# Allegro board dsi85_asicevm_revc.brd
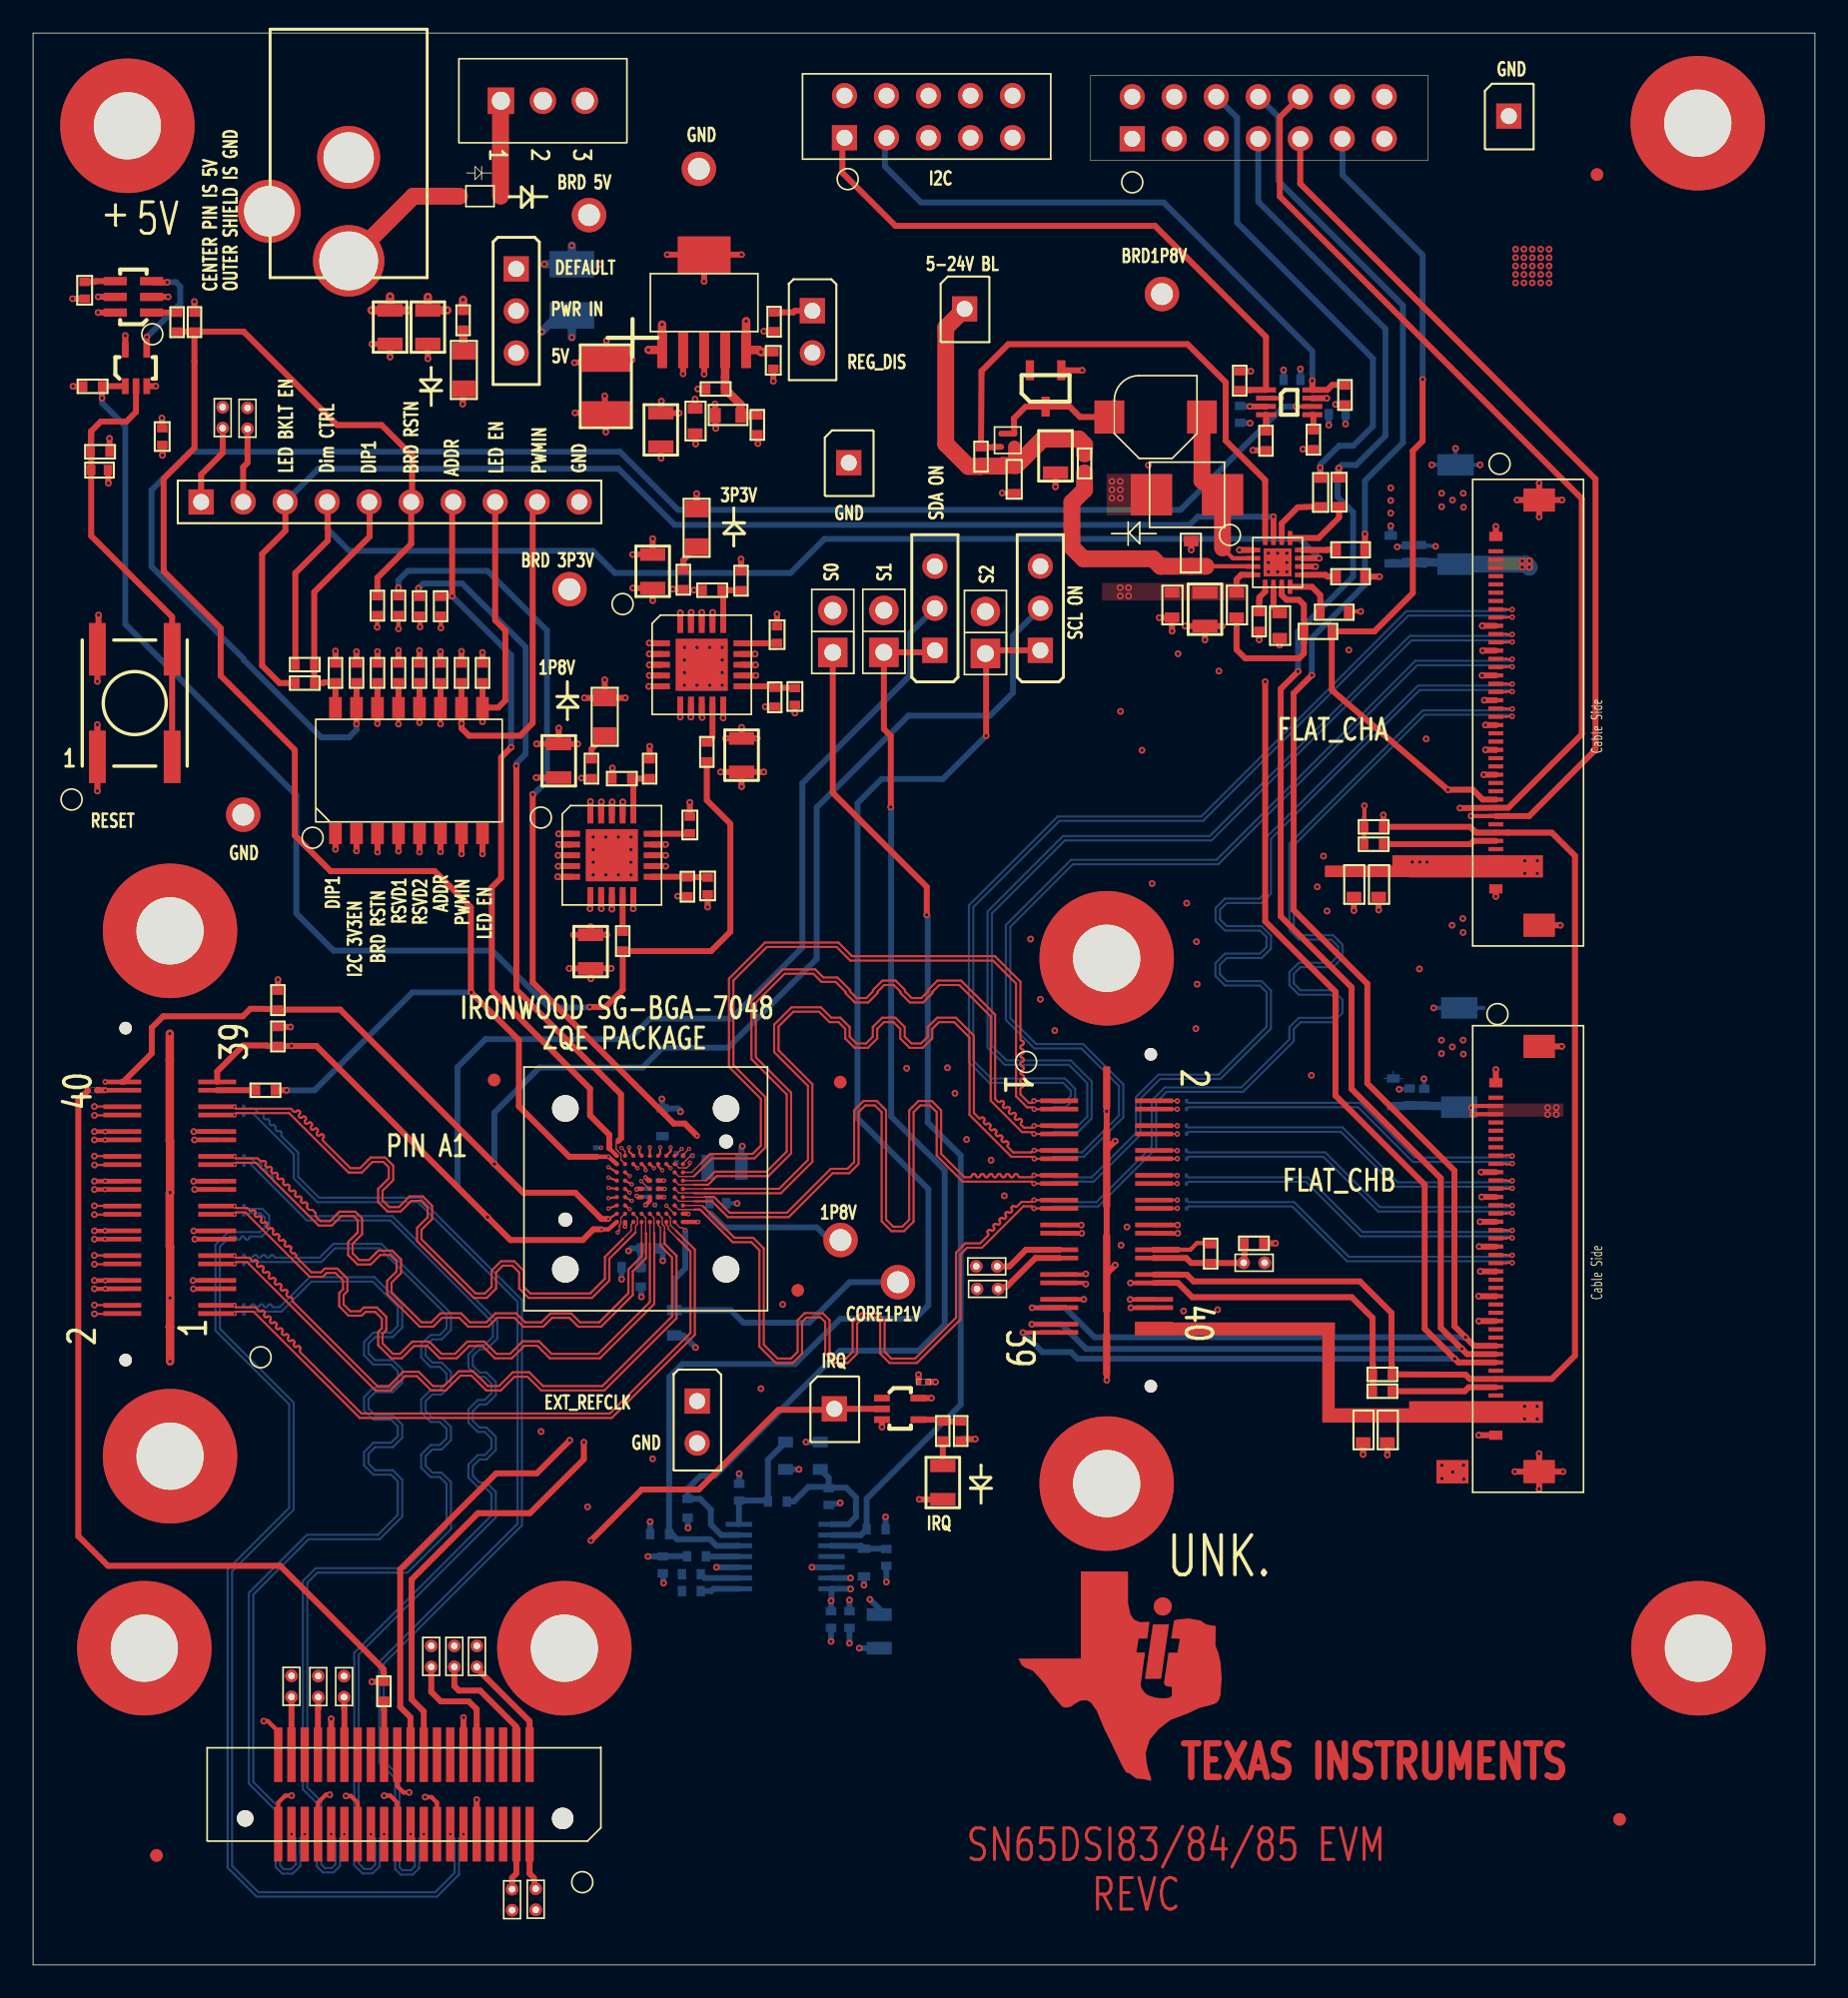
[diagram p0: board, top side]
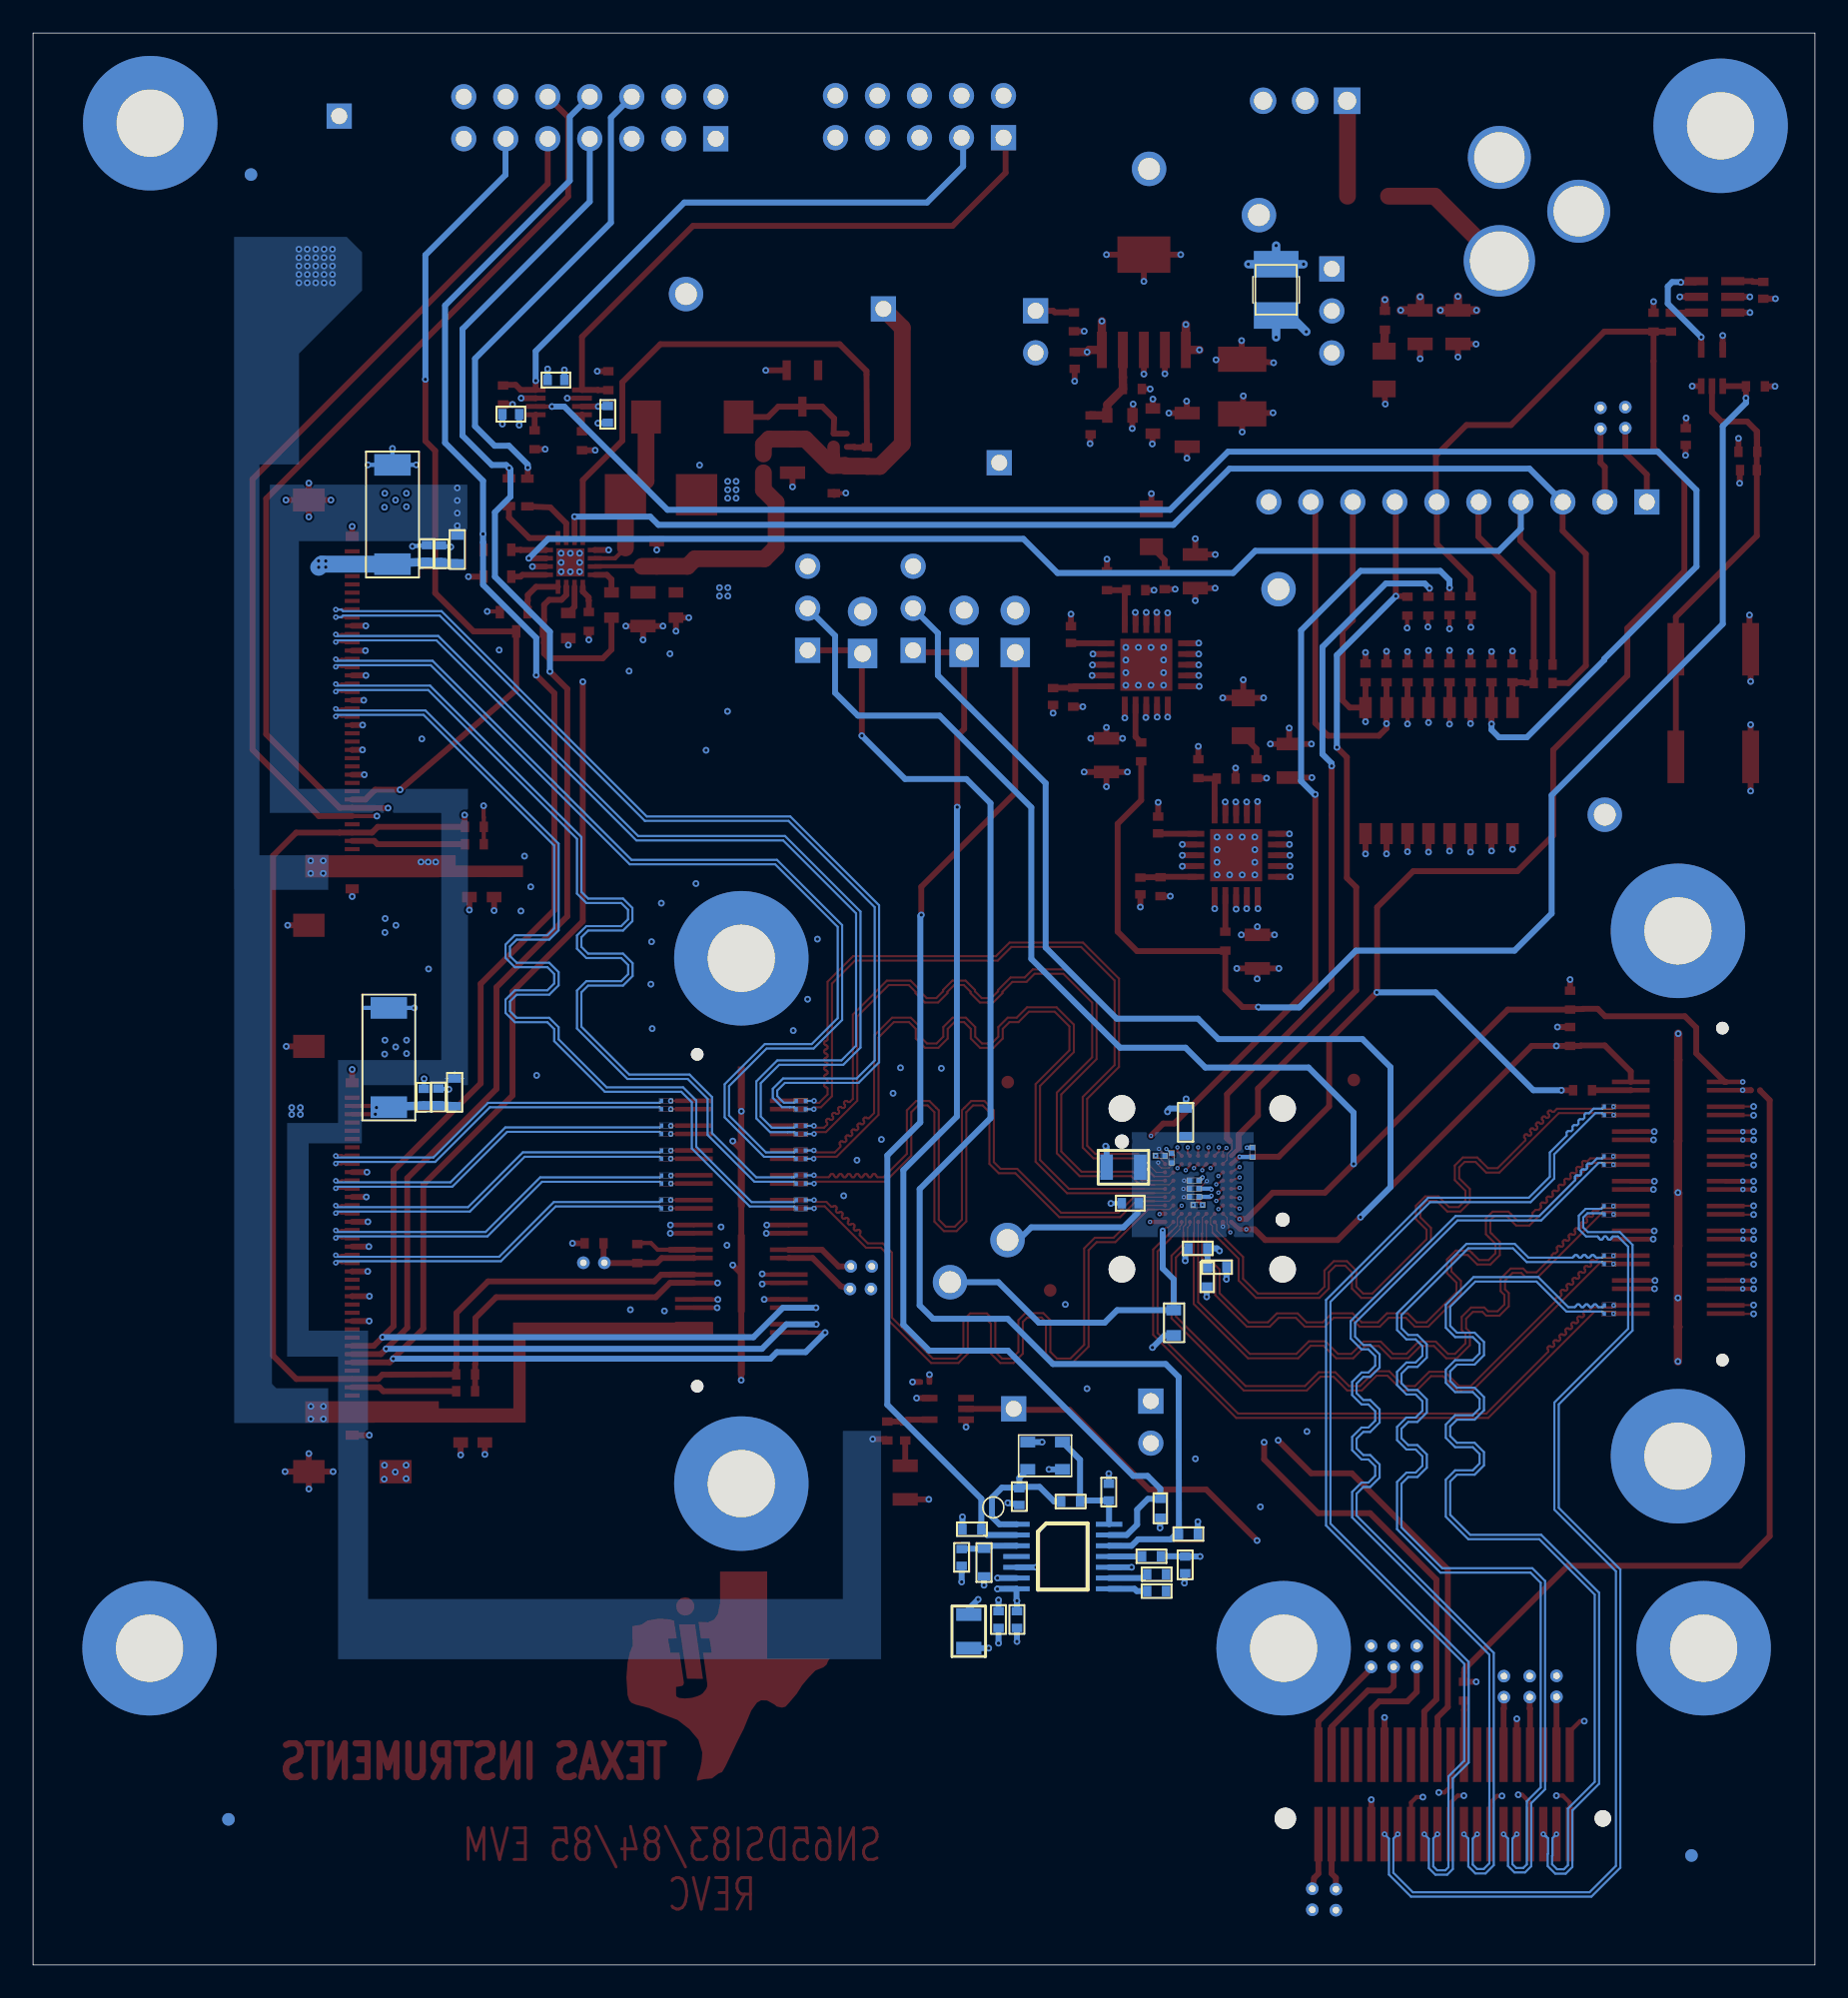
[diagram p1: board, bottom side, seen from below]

Outline 107.75 x 116.75 mm; copper layers: TOP, L2_GND, L3_SIG, L4_PWR, L5_GND, BOTTOM. Coordinates in mm from the lower left corner of the outline.
Outline path: 0,116.75 0,0 107.75,0 107.75,116.75 0,116.75

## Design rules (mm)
net group DIFFPAIR5: nets DSI_A0N DSI_A0P
net group DIFFPAIR6: nets DSI_A1N DSI_A1P
net group DIFFPAIR7: nets DSI_A2N DSI_A2P
net group DIFFPAIR8: nets DSI_A3N DSI_A3P
net group DIFFPAIR9: nets DSI_ACLKN DSI_ACLKP
net group DIFFPAIR10: nets DSI_B0N DSI_B0P
net group DIFFPAIR11: nets DSI_B1N DSI_B1P
net group DIFFPAIR12: nets DSI_B2N DSI_B2P
net group DIFFPAIR13: nets DSI_B3N DSI_B3P
net group DIFFPAIR14: nets DSI_BCLKN DSI_BCLKP
net group DIFFPAIR15: nets FLATA_20455_CLKN FLATA_20455_CLKP
net group DIFFPAIR16: nets FLATA_20455_YN0 FLATA_20455_YP0
net group DIFFPAIR17: nets FLATA_20455_YN1 FLATA_20455_YP1
net group DIFFPAIR18: nets FLATA_20455_YN2 FLATA_20455_YP2
net group DIFFPAIR19: nets FLATA_20455_YN3 FLATA_20455_YP3
net group DIFFPAIR20: nets FLATB_20455_CLKN FLATB_20455_CLKP
net group DIFFPAIR21: nets FLATB_20455_YN0 FLATB_20455_YP0
net group DIFFPAIR22: nets FLATB_20455_YN1 FLATB_20455_YP1
net group DIFFPAIR23: nets FLATB_20455_YN2 FLATB_20455_YP2
net group DIFFPAIR24: nets FLATB_20455_YN3 FLATB_20455_YP3
net group DIFFPAIR25: nets FLATCHA_CLKN FLATCHA_CLKP
net group DIFFPAIR26: nets FLATCHA_Y0N FLATCHA_Y0P
net group DIFFPAIR27: nets FLATCHA_Y1N FLATCHA_Y1P
net group DIFFPAIR28: nets FLATCHA_Y2N FLATCHA_Y2P
net group DIFFPAIR29: nets FLATCHA_Y3N FLATCHA_Y3P
net group DIFFPAIR30: nets FLATCHB_CLKN FLATCHB_CLKP
net group DIFFPAIR31: nets FLATCHB_Y0N FLATCHB_Y0P
net group DIFFPAIR32: nets FLATCHB_Y1N FLATCHB_Y1P
net group DIFFPAIR33: nets FLATCHB_Y2N FLATCHB_Y2P
net group DIFFPAIR34: nets FLATCHB_Y3N FLATCHB_Y3P
net group DIFFPAIR35: nets FX_CLKN FX_CLKP
net group DIFFPAIR36: nets FX_N0 FX_P0
net group DIFFPAIR37: nets FX_N1 FX_P1
net group DIFFPAIR38: nets FX_N2 FX_P2
net group DIFFPAIR39: nets FX_N3 FX_P3
net group H_DDSS: nets GPIO I2C_SCL PWM1 TIMER_PWM

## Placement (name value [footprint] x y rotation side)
C1  10uF  [CC0805]  40.8 48.21 0 bottom
C2  1.0uF  [CC0402]  40.85 46.02 0 bottom
C3  0.01uF  [CC0201]  37.82 47.4 180 bottom
C4  0.1uF  [CC0201]  37.6 45.93 180 bottom
C5  0.01uF  [CC0201]  37.82 46.92 180 bottom
C6  0.1uF  [CC0201]  39.31 48.91 0 bottom
C7  0.01uF  [CC0201]  37.81 46.42 180 bottom
C8  0.1uF  [CC0201]  38.9 48.49 90 bottom
C9  0.1uF  [CC0201]  53.55 35.23 0 top
C10  DNI  [CC0201]  34.01 48.83 90 bottom
C11  1uF  [CC0603]  38.78 39.57 270 bottom
C12  100uF  [CC6032]  86.02 87.66 90 bottom
C13  1.0uF  [CC0402]  83.95 84.75 90 bottom
C14  0.1uF  [CC0402]  83.1 84.73 90 bottom
C15  DNI  [CC0603]  79.87 66.06 270 top
C16  DNI  [CC0603]  81.37 66.06 270 top
C17  100uF  [CC6032]  86.24 54.84 90 bottom
C18  1.0uF  [CC0402]  84.14 51.88 90 bottom
C19  0.1uF  [CC0402]  83.26 51.9 90 bottom
C20  DNI  [CC0603]  81.9 33.1 270 top
C21  DNI  [CC0603]  80.43 33.1 270 top
C22  220pF  [CC0402]  3.14 101.77 270 top
C23  0.1uF  [CC0402]  7.83 92.93 270 top
C24  18pF  [CC0402]  3.46 90.36 0 top
C25  DNI  [CC0402]  48.13 27.75 90 bottom
C26  DNI  [CC0402]  42.69 29.13 270 bottom
C27  22uF  [CC0805]  51.17 21.18 270 bottom
C28  1.0uF  [CC0402]  78.31 93.71 0 bottom
C29  0.1uF  [CC0402]  76.69 95.81 180 bottom
C30  0.1uF  [CC0402]  72.98 94.27 270 bottom
C31  0.1uF  [CC0402]  51.58 25.19 270 bottom
C32  0.1uF  [CC0402]  49.35 21.43 270 bottom
C33  0.1uF  [CC0402]  48.24 21.43 270 bottom
C34  DNI  [CC0603]  40.04 94.07 270 top
C35  10uF  [CC0805]  21.59 100 270 top
C36  22uF  [CC0805]  23.87 100 270 top
C37  22uF  [CC0805]  37.96 93.79 270 top
C38  10uF  [CC1210]  34.64 97.04 270 top
C39  10uF  [CC0805]  42.84 74.13 270 top
C40  1uF  [CC0402]  44.78 97.53 270 top
C41  DNI  [CC0603]  41.27 93.65 0 top
C42  10uF  [CC0805]  37.47 83.21 90 top
C43  0.01uF  [CC0402]  46.09 77.22 270 top
C44  DNI  [CC0402]  44.98 79.84 90 top
C45  10uF  [CC0805]  33.72 62.26 270 top
C46  10uF  [CC0805]  31.79 71.76 90 top
C47  0.01uF  [CC0402]  40.81 65.77 270 top
C48  DNI  [CC0402]  39.7 68.34 90 top
C49  4.7uF  [CC0805]  61.83 92.22 270 top
C50  4.7uF  [CC0805]  70.87 82.95 270 top
C51  0.1uF  [CC0603]  68.88 82.95 270 top
C52  DNI  [CC0603]  72.78 82.95 270 top
C53  1uF  [CC0603]  70.04 84.53 90 top
C54  0.1uF  [CC0603]  75.39 81.71 270 top
C55  0.1uF  [CC0402]  38.07 24.74 270 bottom
D1  LED Orange 0805  [CC0805]  55.01 30.17 270 top
D2  10V, 3A  [SOD323]  27.03 106.9 180 top
D3  LED Green 0805  [R0805]  26.05 97.54 270 top
D4  B150  [SMB-B150]  69.78 88.85 0 top
D5  FYV0704S  [SOT23]  61.23 95.28 90 top
D6  LED RED 0805  [R0805]  40.13 85.71 90 top
D7  LED YLW 0805  [R0805]  34.57 74.29 90 top
FB1  220 @ 100MHZ  [R0603]  38.06 51.76 270 bottom
FB2  220 @ 100MHZ  [R0603]  82.1 86.38 270 bottom
FB3  220 @ 100MHZ  [R0603]  82.26 53.57 270 bottom
FB4  220 @ 100MHZ  [R0603]  50.25 25.15 270 bottom
FB5  DNI  [R1210]  32.58 101.24 90 bottom
FB6  220 @ 100MHZ  [R0603]  59.33 88.95 90 top
J1  FX6A-40S-0.8SV2(71)  [IPEX_20006_40PIN]  22.43 10.3 0 top
J2  I-PEX 20455-040E-12  [IPEX_20455_40PIN]  90.26 75.68 90 top
J3  HEADER 7X2 100mil Thru-hole  [BERG2X7]  66.47 110.37 90 top
J4  QSH-020-01  [QSH-020_X]  8.26 56.62 90 top
J5  I-PEX 20455-040E-12  [IPEX_20455_40PIN]  90.26 42.66 90 top
J6  QSH-020-01  [QSH-020_X]  64.92 34.97 270 top
J7  HDR2X1 M .1  [HDR_2X1]  48.36 79.32 0 top
J8  HDR2X1 M .1  [HDR_2X1]  51.45 79.33 0 top
J10  Header 5x2 0.1" thru-hole  [BERG2X5]  49.07 110.43 90 top
J11  HDR2X1 M .1  [HDR_2X1]  57.59 79.26 0 top
J13  2.1mm x 5.5mm  [PJ-202AH]  19.08 102.99 180 top
J14  HDR2X1 M .1  [BERG1X2]  47.13 99.97 0 top
J15  HDR3X1 M .1  [BERG1X3]  29.22 102.5 0 top
J16  HEADER 1x10  [BERG1X10]  20.31 88.42 90 top
J17  HDR2X1 M .1  [BERG1X2]  40.16 34.07 0 top
J18  HDR3X1 M .1  [BERG1X3]  54.53 79.45 180 top
J19  HDR3X1 M .1  [BERG1X3]  60.91 79.45 180 top
L1  10uH  [IND_CDPH4D19F]  67.89 93.55 180 top
LP1  LP  [TESTLOOP]  68.27 100.98 0 top
LP2  LP  [TESTLOOP]  48.83 43.81 0 top
LP3  LP  [TESTLOOP]  52.3 41.26 0 top
LP4  LP  [TESTLOOP]  12.71 69.51 0 top
LP5  LP  [TESTLOOP]  40.27 108.55 0 top
LP6  LP  [TESTLOOP]  33.62 105.75 0 top
LP7  LP  [TESTLOOP]  32.44 83.14 0 top
NOREF  -  [unnamed]  46.25 40.77 0 top
NOREF#2  -  [unnamed#2]  64.92 29.09 0 top
NOREF#3  -  [unnamed#2]  100.67 111.31 0 top
NOREF#4  -  [unnamed#2]  64.92 60.84 0 top
NOREF#5  -  [unnamed]  7.47 6.61 0 top
NOREF#6  -  [unnamed#2]  6.73 19.14 0 top
NOREF#7  -  [unnamed]  27.88 53.48 0 top
NOREF#8  -  [unnamed#2]  32.13 19.14 0 top
NOREF#9  -  [unnamed]  95.94 8.8 0 top
NOREF#10  -  [#3]  0 0 90 top
NOREF#11  -  [unnamed]  94.58 108.2 0 top
NOREF#12  -  [unnamed]  48.81 53.35 0 top
NOREF#13  -  [unnamed#2]  8.28 62.5 0 top
NOREF#14  -  [unnamed#2]  100.71 19.14 0 top
NOREF#15  -  [unnamed#2]  8.28 30.75 0 top
NOREF#16  -  [unnamed#2]  5.7 111.15 0 top
NOREF#17  -  [#3]  0 116.75 0 top
NOREF#18  -  [unnamed]  94.58 108.2 180 bottom
NOREF#19  -  [unnamed]  7.47 6.61 180 bottom
NOREF#20  -  [unnamed]  95.94 8.8 180 bottom
Q1  Si8409DB  [MFP_4]  58.94 92.15 0 top
R1  0  [R0402]  56.1 31.7 90 top
R2  350  [R0402]  55.01 31.7 90 top
R3  4.7K  [R0402]  14.81 58.88 270 top
R4  4.7K  [R0402]  14.81 56.69 270 top
R5  10K  [R0402]  36.75 43.31 0 bottom
R6  0  [R0201]  12.18 45.36 0 bottom
R7  0  [R0201]  12.19 45.86 0 bottom
R8  0  [R0201]  12.18 51.37 0 bottom
R9  0  [R0201]  12.18 51.87 0 bottom
R10  0  [R0201]  12.19 48.36 0 bottom
R11  0  [R0201]  12.19 48.87 0 bottom
R12  0  [R0201]  12.18 42.37 0 bottom
R13  0  [R0201]  12.19 42.87 0 bottom
R14  0  [R0201]  12.18 39.36 0 bottom
R15  0  [R0201]  12.17 39.86 0 bottom
R16  DNI  [R0402]  21.22 15.97 90 top
R17  0  [R0201]  61.04 52.22 0 bottom
R18  0  [R0201]  61.05 51.72 0 bottom
R19  0  [R0201]  61.05 50.72 0 bottom
R20  0  [R0201]  61.04 50.22 0 bottom
R21  0  [R0201]  61.05 49.22 0 bottom
R22  0  [R0201]  61.05 48.72 0 bottom
R23  0  [R0201]  61.05 47.72 0 bottom
R24  0  [R0201]  61.04 47.22 0 bottom
R25  0  [R0201]  61.04 45.72 0 bottom
R26  0  [R0201]  61.04 46.22 0 bottom
R27  DNI  [R0402]  81.64 68.78 180 top
R28  0  [R0402]  81.64 67.73 180 top
R29  0  [R0402]  13.48 52.86 0 top
R39  0  [R0201]  69.19 51.72 0 bottom
R40  0  [R0201]  69.18 50.73 0 bottom
R41  0  [R0201]  69.19 50.22 0 bottom
R42  0  [R0201]  69.19 52.22 0 bottom
R43  0  [R0201]  69.19 48.73 0 bottom
R44  0  [R0201]  69.18 49.21 0 bottom
R45  0  [R0201]  69.18 47.71 0 bottom
R46  0  [R0201]  69.18 47.22 0 bottom
R47  0  [R0201]  69.19 46.23 0 bottom
R48  0  [R0201]  69.19 45.72 0 bottom
R49  DNI  [R0402]  82.17 35.69 180 top
R50  0  [R0402]  82.17 34.67 180 top
R51  DNI  [R0402]  9.76 99.86 270 top
R52  0  [R0402]  8.71 98.71 90 top
R53  1K  [R0402]  4.62 91.45 180 top
R54  4.7K  [R0402]  18.29 77.52 90 top
R55  4.7K  [R0402]  19.56 77.52 90 top
R56  4.7K  [R0402]  20.83 77.52 90 top
R57  4.7K  [R0402]  22.1 77.52 90 top
R58  4.7K  [R0402]  23.37 77.52 90 top
R59  4.7K  [R0402]  24.64 77.52 90 top
R60  4.7K  [R0402]  25.91 77.52 90 top
R61  4.7K  [R0402]  27.18 77.52 90 top
R62  DNI  [R0402]  22.1 81.58 90 top
R63  0  [R0402]  17 77.47 180 top
R64  DNI  [R0402]  20.82 81.58 90 top
R65  DNI  [R0402]  23.37 81.55 90 top
R66  DNI  [R0402]  45.58 28 180 bottom
R67  18  [R0402]  39.55 24.7 0 bottom
R68  18  [R0402]  39.24 23.61 0 bottom
R69  18  [R0402]  39.24 22.59 0 bottom
R70  0  [R0201]  3.87 52.87 180 top
R71  0  [R0402]  24.64 81.55 90 top
R72  10K  [R0402]  37.32 26.04 0 bottom
R73  10K  [R0402]  39.59 27.03 90 bottom
R74  10K  [R0402]  51.55 26.33 180 bottom
R75  0  [R0402]  77.42 91.61 90 top
R76  0  [R0402]  74.56 91.54 90 top
R77  4.7K  [R0402]  72.97 96.32 270 top
R78  4.7K  [R0402]  79.33 94.31 90 top
R79  4.7K  [R0402]  44.85 76.04 90 top
R80  0  [R0402]  40.74 72.74 90 top
R81  500  [R0402]  26 98.83 90 top
R82  3.57K  [R0402]  41.64 83.09 180 top
R83  37.4K  [R0402]  41.85 95.25 180 top
R84  1.15K  [R0402]  42.81 84.23 270 top
R85  13K  [R0402]  43.8 92.5 90 top
R86  4.7K  [R0402]  44.81 99.88 270 top
R87  4.7K  [R0402]  39.57 64.59 90 top
R88  0  [R0402]  35.66 61.3 90 top
R89  3.57K  [R0402]  36.18 71.7 180 top
R90  2.87K  [R0402]  37.29 72.87 270 top
R91  100K  [R0402]  57.32 91.73 270 top
R92  51  [R0402]  63.59 90.18 90 top
R93  62K  [R0402]  74.14 80.63 90 top
R94  DNI  [R0603]  77.86 89.83 270 top
R95  DNI  [R0603]  78.98 89.84 270 top
R96  DNI  [R0603]  80.51 85.53 180 top
R97  DNI  [R0603]  80.51 83.9 180 top
R98  DNI  [R0603]  79.52 81.76 180 top
R99  DNI  [R0603]  78.54 80.59 180 top
R100  DNI  [R0402]  17 78.59 180 top
R101  350  [R0402]  39.32 84.29 270 top
R102  150  [R0402]  33.77 72.87 270 top
R103  10K  [R0402]  4.17 95.41 180 top
R104  DNI  [R0402]  35.59 42.17 0 bottom
R105  0  [R0402]  36.75 41 90 bottom
R106  0  [R0402]  74.4 43.61 180 top
R107  DNI  [R0402]  71.21 43.56 270 top
SW1  PB_SWITCH  [SW_MOM_2NO]  6.15 76.26 0 top
SW2  8-POS 50-MIL SMT  [TDA08H0SK1]  22.73 72.18 0 top
SW6  -  [TS01CQE]  28.29 112.67 270 top
TP1  T POINT S  [BERG1X1]  48.46 33.61 0 top
TP4  T POINT S  [BERG1X1]  56.33 100.08 0 top
TP5  T POINT S  [BERG1X1]  49.33 90.79 0 top
TP6  T POINT S  [BERG1X1]  89.24 111.74 0 top
U1  SN65DSI85  [IRONWOOD_81PIN_7048]  32.19 51.76 180 top
U2  SN74LVC1G07DCK  [DCK5]  52.43 33.61 0 top
U3  TPS3808  [DBV_R-PDSO-G6]  6.07 100.81 180 top
U4  SN74LVC1G08DCK  [DCK5]  6.23 96.52 90 top
U5  CDCEL913PW  [PW14]  45.49 24.68 180 bottom
U6  txs0102dcut  [DCU8]  75.96 94.44 0 top
U7  REG104-A  [DCQ_R-PDSO-G6]  40.58 100.47 90 top
U8  TPS74201RGWT  [RGW20]  40.44 78.58 0 top
U9  TPS74201RGWT  [RGW20]  35 67.06 0 top
U10  TPS61181A-QFN16  [RTE_16PIN]  75.26 84.76 0 top
UNK.  -  [#3]  65.57 17.13 0 top
XC1  XC  [JMP_2P]  30.4 3.33 90 top
XC2  XC  [JMP_2P]  28.97 3.31 90 top
XC3  XC  [JMP_2P]  25.47 18.01 90 top
XC4  XC  [JMP_2P]  26.84 18.01 90 top
XC5  XC  [JMP_2P]  24.08 18.01 90 top
XC6  XC  [JMP_2P]  18.81 16.18 90 top
XC7  XC  [JMP_2P]  17.25 16.18 90 top
XC8  XC  [JMP_2P]  15.63 16.2 90 top
XC9  XC  [JMP_2P]  57.04 42.22 0 top
XC11  XC  [JMP_2P]  57.08 40.85 0 top
XC12  XC  [JMP_2P]  73.21 42.44 0 top
XC14  XC  [JMP_2P]  12.97 92.84 90 top
XC15  XC  [JMP_2P]  11.47 92.88 90 top
Y1  27MHZ _crystal  [ABM8]  46.55 30.77 270 bottom

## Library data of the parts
C1-C34 C41 C43 C44 C47 C48 C55 = CAP NP
C35-C39 C42 C45 C46 C49 C50 = CAP_0
C40 = cc0402
C51-C53 = CAPACITOR NON-POL
C54 = 0.1uFCapacitor10V10%0402
D1 D3 D6 D7 = DIODE
D2 = BAT60A
D4 = DIODE SCHOTTKY_0
D5 = FYV0704S_SOT23
FB1-FB4 FB6 = FERRITE BEAD
FB5 = FB1210_0
J1 = 111-1003780_1
J2 J5 = IPEX LVDS Conn_1
J3 = HEADER 7X2_0
J4 J6 = QSH-020-01_3
J7 J8 J11 J14 J17 = HDR2X1 M .1
J10 = CONN PCB 5x2-S
J13 = BNC_2
J15 J18 J19 = HDR3X1 M .1
J16 = HEADER 10
L1 = INDUCTOR
LP1-LP7 = TESTLOOP
NOREF NOREF#5 NOREF#7 NOREF#9 NOREF#11 NOREF#12 NOREF#18-NOREF#20 = -: User Part Number: D*
Q1 = Si8409DB_0
R1-R29 R39-R107 = R_4
SW1 = PB_SWITCH_0
SW2 = SW DIP-8/SM_0
SW6 = SW_SLIDE_SPDT2
TP1 TP4-TP6 = T POINT S
U1 = SN65DSI85
U2 = SN74LVC1G07_0
U3 = TPS3808
U4 = SN74AHC1G08DCK_2
U5 = CDCEL913PW
U6 = txs0102dcut_2
U7 = REG104_0
U8 U9 = TPS74401RGWT_0
U10 = TPS61181A-QFN16
XC1-XC9 XC11 XC12 XC14 XC15 = XCON_0
Y1 = 27MHZ _crystal

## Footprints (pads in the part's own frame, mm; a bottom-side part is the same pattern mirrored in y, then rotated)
ABM8
  rect 0.65x0.9 smd: 1(-0.825,1.05) 2(-0.825,-1.05) 3(0.825,-1.05) 4(0.825,1.05)
BERG1X1
  rect 1.524x1.524 hole 0.965: 1(0,0)
BERG1X2
  rect 1.524x1.524 hole 0.965: 1(0,0)
  round 1.524 hole 0.965: 2(0,-2.54)
BERG1X3
  rect 1.524x1.524 hole 0.965: 1(0,0)
  round 1.524 hole 0.965: 2(0,-2.54) 3(0,-5.08)
BERG1X10
  rect 1.524x1.524 hole 0.965: 1(0,10.148)
  round 1.524 hole 0.965: 2(0,7.608) 3(0,5.068) 4(0,2.528) 5(0,-0.012) 6(0,-2.552) 7(0,-5.092) 8(0,-7.632) 9(0,-10.172) 10(0,-12.712)
BERG2X5
  rect 1.524x1.524 hole 0.965: 1(0,0)
  round 1.524 hole 0.965: 2(2.54,0) 3(0,-2.54) 4(2.54,-2.54) 5(0,-5.08) 6(2.54,-5.08) 7(0,-7.62) 8(2.54,-7.62) 9(0,-10.16) 10(2.54,-10.16)
BERG2X7
  rect 1.524x1.524 hole 0.965: 1(0,0)
  round 1.524 hole 0.965: 2(2.54,0) 3(0,-2.54) 4(2.54,-2.54) 5(0,-5.08) 6(2.54,-5.08) 7(0,-7.62) 8(2.54,-7.62) 9(0,-10.16) 10(2.54,-10.16) 11(0,-12.7) 12(2.54,-12.7) 13(0,-15.24) 14(2.54,-15.24)
CC0201
  rect 0.305x0.305 smd: 1(0,0) 2(0.559,0)
CC0402
  rect 0.508x0.635 smd: 1(0.051,-0.015) 2(1.067,-0.015)
CC0603
  rect 0.635x0.889 smd: 1(0,0) 2(1.524,0)
CC0805
  rect 0.762x1.524 smd: 1(0,0) 2(2.032,0)
CC1210
  rect 1.524x2.921 smd: 1(0,0) 2(3.302,0)
CC6032
  rect 1.3x2.2 smd: 1(-3,0) 2(3,0)
DBV_R-PDSO-G6
  rect 1.4x0.5 smd: 1(-1.1,0.95) 2(-1.1,0) 3(-1.1,-0.95) 4(1.1,-0.95) 5(1.1,0) 6(1.1,0.95)
DCK5
  rect 0.95x0.4 smd: 1(-1.1,0.65) 2(-1.1,0) 3(-1.1,-0.65) 4(1.1,-0.65) 5(1.1,0.65)
DCQ_R-PDSO-G6
  rect 2.2x0.6 smd: 1(-2.858,2.54) 2(-2.858,1.27) 3(-2.858,0) 4(-2.858,-1.27) 5(-2.858,-2.54)
  rect 2.2x3.2 smd: 6(2.9,0)
DCU8
  rect 1.2x0.3 smd: 1(-1.4,0.75) 2(-1.4,0.25) 3(-1.4,-0.25) 4(-1.4,-0.75) 5(1.4,-0.75) 6(1.4,-0.25) 7(1.4,0.25) 8(1.4,0.75)
HDR_2X1
  rect 1.778x1.778 hole 1.016: 1(0,0)
  round 1.778 hole 1.016: 2(0,2.54)
IND_CDPH4D19F
  rect 1.8x2 smd: 1(-2.8,0) 2(2.8,0)
IPEX_20006_40PIN
  round 1 hole 1 unplated: (-9.6,-1.45)
  round 1.3 hole 1.3 unplated: (9.6,-1.45)
  rect 0.5x3.3 smd: 1(7.6,-2.4) 2(7.6,2.4) 3(6.8,-2.4) 4(6.8,2.4) 5(6,-2.4) 6(6,2.4) 7(5.2,-2.4) 8(5.2,2.4) 9(4.4,-2.4) 10(4.4,2.4) 11(3.6,-2.4) 12(3.6,2.4) 13(2.8,-2.4) 14(2.8,2.4) 15(2,-2.4) 16(2,2.4) 17(1.2,-2.4) 18(1.2,2.4) 19(0.4,-2.4) 20(0.4,2.4) 21(-0.4,-2.4) 22(-0.4,2.4) 23(-1.2,-2.4) 24(-1.2,2.4) 25(-2,-2.4) 26(-2,2.4) 27(-2.8,-2.4) 28(-2.8,2.4) 29(-3.6,-2.4) 30(-3.6,2.4) 31(-4.4,-2.4) 32(-4.4,2.4) 33(-5.2,-2.4) 34(-5.2,2.4) 35(-6,-2.4) 36(-6,2.4) 37(-6.8,-2.4) 38(-6.8,2.4) 39(-7.6,-2.4) 40(-7.6,2.4)
IPEX_20455_40PIN
  rect 0.25x0.9 smd: 1(9.75,1.8) 2(9.25,1.8) 3(8.75,1.8) 4(8.25,1.8) 5(7.75,1.8) 6(7.25,1.8) 7(6.75,1.8) 8(6.25,1.8) 9(5.75,1.8) 10(5.25,1.8) 11(4.75,1.8) 12(4.25,1.8) 13(3.75,1.8) 14(3.25,1.8) 15(2.75,1.8) 16(2.25,1.8) 17(1.75,1.8) 18(1.25,1.8) 19(0.75,1.8) 20(0.25,1.8) 21(-0.25,1.8) 22(-0.75,1.8) 23(-1.25,1.8) 24(-1.75,1.8) 25(-2.25,1.8) 26(-2.75,1.8) 27(-3.25,1.8) 28(-3.75,1.8) 29(-4.25,1.8) 30(-4.75,1.8) 31(-5.25,1.8) 32(-5.75,1.8) 33(-6.25,1.8) 34(-6.75,1.8) 35(-7.25,1.8) 36(-7.75,1.8) 37(-8.25,1.8) 38(-8.75,1.8) 39(-9.25,1.8) 40(-9.75,1.8)
  rect 0.55x0.8 smd: GND1(10.65,1.8) GND2(-10.65,1.8)
  rect 1.4x1.9 smd: GND3(-12.85,-0.82) GND4(12.85,-0.82)
IRONWOOD_81PIN_7048
  round 1.61 hole 1.61 unplated: (-9.72,9.72) (-9.72,0) (0,9.72) (0,0)
  round 0.85 hole 0.85 unplated: (-9.72,2) (0,6.72)
  round 0.254 smd: A1(-3.11,2.86) A2(-3.61,2.86) A3(-4.11,2.86) A4(-4.61,2.86) A5(-5.11,2.86) A6(-5.61,2.86) A7(-6.11,2.86) A8(-6.61,2.86) A9(-7.11,2.86) B1(-3.11,3.36) B2(-3.61,3.36) B3(-4.11,3.36) B4(-4.61,3.36) B5(-5.11,3.36) B6(-5.61,3.36) B7(-6.11,3.36) B8(-6.61,3.36) B9(-7.11,3.36) C1(-3.11,3.86) C2(-3.61,3.86) C8(-6.61,3.86) C9(-7.11,3.86) D1(-3.11,4.36) D2(-3.61,4.36) D5(-5.11,4.36) D6(-5.61,4.36) D8(-6.61,4.36) D9(-7.11,4.36) E1(-3.11,4.86) E2(-3.61,4.86) E4(-4.61,4.86) E5(-5.11,4.86) E6(-5.61,4.86) E8(-6.61,4.86) E9(-7.11,4.86) F1(-3.11,5.36) F2(-3.61,5.36) F4(-4.61,5.36) F5(-5.11,5.36) F6(-5.61,5.36) F8(-6.61,5.36) F9(-7.11,5.36) G1(-3.11,5.86) G2(-3.61,5.86) G8(-6.61,5.86) G9(-7.11,5.86) H1(-3.11,6.36) H2(-3.61,6.36) H3(-4.11,6.36) H4(-4.61,6.36) H5(-5.11,6.36) H6(-5.61,6.36) H7(-6.11,6.36) H8(-6.61,6.36) H9(-7.11,6.36) J1(-3.11,6.86) J2(-3.61,6.86) J3(-4.11,6.86) J4(-4.61,6.86) J5(-5.11,6.86) J6(-5.61,6.86) J7(-6.11,6.86) J8(-6.61,6.86) J9(-7.11,6.86)
JMP_2P
  round 0.762 hole 0.406: 1(0,0) 2(1.27,0)
MFP_4
  round 0.3 smd: 1(-0.4,-0.4) 2(-0.4,0.4) 3(0.4,0.4) 4(0.4,-0.4)
PJ-202AH
  round 4.318 hole 3.556: 1(0,0)
  round 3.81 hole 3.048: 2(4.801,-2.997) 3(0,-6.248)
PW14
  rect 1.6x0.3 smd: 1(-2.8,1.95) 2(-2.8,1.3) 3(-2.8,0.65) 4(-2.8,0) 5(-2.8,-0.65) 6(-2.8,-1.3) 7(-2.8,-1.95) 8(2.8,-1.95) 9(2.8,-1.3) 10(2.8,-0.65) 11(2.8,0) 12(2.8,0.65) 13(2.8,1.3) 14(2.8,1.95)
QSH-020_X
  round 0.762 hole 1.016 unplated: (-20.06,2.67) (0,2.67)
  rect 0.279x2.286 smd: 1(-17.25,-2.87) 2(-17.25,2.87) 3(-16.75,-2.87) 4(-16.75,2.87) 5(-15.75,-2.87) 6(-15.75,2.87) 7(-15.25,-2.87) 8(-15.25,2.87) 9(-14.25,-2.87) 10(-14.25,2.87) 11(-13.75,-2.87) 12(-13.75,2.87) 13(-12.75,-2.87) 14(-12.75,2.87) 15(-12.25,-2.87) 16(-12.25,2.87) 17(-11.25,-2.87) 18(-11.25,2.87) 19(-10.75,-2.87) 20(-10.75,2.87) 21(-9.75,-2.87) 22(-9.75,2.87) 23(-9.25,-2.87) 24(-9.25,2.87) 25(-8.25,-2.87) 26(-8.25,2.87) 27(-7.75,-2.87) 28(-7.75,2.87) 29(-6.75,-2.87) 30(-6.75,2.87) 31(-6.25,-2.87) 32(-6.25,2.87) 33(-5.25,-2.87) 34(-5.25,2.87) 35(-4.75,-2.87) 36(-4.75,2.87) 37(-3.75,-2.87) 38(-3.75,2.87) 39(-3.25,-2.87) 40(-3.25,2.87)
  rect 2.54x0.432 smd: G1(-18.06,0) G4(-1.93,0)
  rect 4.699x0.432 smd: G2(-13.17,0) G3(-6.82,0)
R0201
  rect 0.203x0.254 smd: 1(0,0) 2(0.559,0)
R0402
  rect 0.508x0.635 smd: 1(0,0) 2(1.143,0)
R0603
  rect 0.508x0.762 smd: 1(0,0) 2(1.676,0)
R0805
  rect 1.016x1.397 smd: 1(0,0) 2(2.286,0)
R1210
  rect 1.6x2.7 smd: 1(-1.55,0) 2(1.55,0)
RGW20
  rect 1.016x0.356 smd: 1(-2.433,1.301) 2(-2.433,0.65) 3(-2.433,0) 4(-2.433,-0.65) 5(-2.433,-1.301) 11(2.433,-1.301) 12(2.433,-0.65) 13(2.433,0) 14(2.433,0.65) 15(2.433,1.301)
  rect 0.356x1.016 smd: 6(-1.301,-2.433) 7(-0.65,-2.433) 8(0,-2.433) 9(0.65,-2.433) 10(1.301,-2.433) 16(1.301,2.433) 17(0.65,2.433) 18(0,2.433) 19(-0.65,2.433) 20(-1.301,2.433)
  rect 3.15x3.15 smd: 21(0,0)
RTE_16PIN
  rect 0.85x0.28 smd: 1(-1.475,0.75) 2(-1.475,0.25) 3(-1.475,-0.25) 4(-1.475,-0.75) 9(1.475,-0.75) 10(1.475,-0.25) 11(1.475,0.25) 12(1.475,0.75)
  rect 0.28x0.85 smd: 5(-0.75,-1.475) 6(-0.25,-1.475) 7(0.25,-1.475) 8(0.75,-1.475) 13(0.75,1.475) 14(0.25,1.475) 15(-0.25,1.475) 16(-0.75,1.475)
  rect 1.7x1.7 smd: 17(0,0)
SMB-B150
  rect 2.5x2.5 smd: 1(2.15,0) 2(-2.15,0)
SOD323
  rect 0.8x0.55 smd: 1(-1.24,0) 2(1.24,0)
SOT23
  rect 1.2x0.5 smd: 1(1.1,-0.95) 2(1.1,0.95) 3(-1.1,0)
SW_MOM_2NO
  rect 1.016x3.175 smd: 1(-2.261,-3.251) 2(-2.261,3.251) 3(2.261,-3.251) 4(2.261,3.251)
TDA08H0SK1
  rect 0.762x1.27 smd: 1(-4.445,-3.81) 2(-3.175,-3.81) 3(-1.905,-3.81) 4(-0.635,-3.81) 5(0.635,-3.81) 6(1.905,-3.81) 7(3.175,-3.81) 8(4.445,-3.81) 9(4.445,3.81) 10(3.175,3.81) 11(1.905,3.81) 12(0.635,3.81) 13(-0.635,3.81) 14(-1.905,3.81) 15(-3.175,3.81) 16(-4.445,3.81)
TESTLOOP
  round 2.083 hole 1.321: 1(0,0)
TS01CQE
  rect 1.6x1.6 hole 1.092: 1(0,0)
  round 1.6 hole 1.092: 2(0,2.54) 3(0,5.08)
unnamed
  round 0.762 smd: 1(0,0)
unnamed#2
  round 8.128 hole 4.064: (0,0)

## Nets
5V_AJD: C41.2 R83.1 R85.2 U7.4(NR/ADJUST)
9V_DIODE: D2.2(A) J13.1(T)
GND: C1.2 C2.2 C3.2 C4.2 C5.2 C6.2 C7.2 C8.2 C9.2 C10.2 C11.2 C12.2 C13.2 C14.2 C15.2 C16.2 C17.2 C18.2 C19.2 C20.2 C21.2 C22.2 C23.2 C24.2 C25.1 C26.1 C27.2 C28.2 C29.2 C30.2 C31.2 C32.2 C33.2 C34.2 C35.2 C36.2 C37.2 C38.2 C39.2 C40.2 C42.2 C43.2 C44.2 C45.2 C46.2 C47.2 C48.2 C49.2 C50.2 C51.2 C53.2 C54.2 C55.2 D1.2(K) D3.2(K) D5.1(ANODE) D6.2(K) D7.2(K) J1.9(P9) J1.12(P12) J1.15(P15) J1.21(P21) J1.22(P22) J1.27(P27) J1.32(P32) J1.33(P33) J1.39(P39) J1.40(P40) J2.10 J2.13 J2.16 J2.19 J2.22 J2.25 J2.28 J2.GND1 J2.GND2 J2.GND3 J2.GND4 J3.12 J3.13 J3.14 J4.5 J4.6 J4.7 J4.8 J4.13 J4.14 J4.15 J4.16 J4.21 J4.22 J4.23 J4.24 J4.29 J4.30 J4.31 J4.32 J4.G1 J4.G2 J4.G3 J4.G4 J5.10 J5.13 J5.16 J5.19 J5.22 J5.25 J5.28 J5.GND1 J5.GND2 J5.GND3 J5.GND4 J6.21 J6.22 J6.23 J6.24 J6.34 J6.36 J6.G1 J6.G2 J6.G3 J6.G4 J7.2 J8.2 J10.2(6) J10.10 J11.2 J13.2(S) J13.3(SW) J16.10 J17.2 J18.3 J19.3 LP4.1 LP5.1 R5.2 R84.1 R85.1 R86.2 R90.1 R93.1 SW1.1(A) SW1.2(A_) SW2.1(A1) SW2.2(A2) SW2.3(A3) SW2.4(A4) SW2.5(A5) SW2.6(A6) SW2.7(A7) SW2.8(A8) TP5.1(TP) TP6.1(TP) U1.A2(GND#A2) U1.A8(GND#A8) U1.B9(GND#B9) U1.D5(GND#D5) U1.E4(GND#E4) U1.F4(GND#F4) U1.F5(GND#F5) U1.H9(GND#H9) U2.3(GND) U3.2(GND) U4.3(GND) U5.5(GND#5) U5.10(GND#10) U6.2(GND) U7.3(GND#3) U7.6(GND#6) U8.2(NC#2) U8.3(NC#3) U8.4(NC#4) U8.12(GND) U8.13(NC#13) U8.14(NC#14) U8.17(NC#17) U8.21(PAD) U9.2(NC#2) U9.3(NC#3) U9.4(NC#4) U9.12(GND) U9.13(NC#13) U9.14(NC#14) U9.17(NC#17) U9.21(PAD) U10.1(PGND) U10.10(GND) U10.17(PAD) Y1.2 Y1.4
VCC_1P8V: C1.1 C2.1 C3.1 C4.1 C5.1 C6.1 C7.1 C8.1 FB1.2 LP2.1 U1.A9(VCC#A9) U1.B8(VCC#B8) U1.D6(VCC#D6) U1.E5(VCC#E5) U1.E6(VCC#E6) U1.F6(VCC#F6) U1.J2(VCC#J2)
A1_SCL: R76.2 U6.4(A2)
A1_SDA: R75.2 U6.5(A1)
ADDR: J16.7 R71.2 U1.A1(ADDR)
ADDR_DIP: R59.1 R71.1 SW2.11(B6)
BKLT_CIN: C54.1 U10.6(CIN)
BKLT_FLT: Q1.1(GATE) R91.1 U10.16(FLT)
BKLT_IFB1: C52.2 R99.2 U10.7(IFB1)
BKLT_IFB2: R98.2 U10.8(IFB2)
BKLT_IFB3: R97.2 U10.9(IFB3)
BKLT_IFB4: R96.2 U10.12(IFB4)
BKLT_IFB5: R95.2 U10.13(IFB5)
BKLT_IFB6: R94.2 U10.14(IFB6)
BKLT_ISET: R93.2 U10.5(ISET)
BKLT_SW: D4.1(ANODE) L1.1 U10.2(SW)
BKLT_VBAT: C53.1 R92.1 U10.3(VBAT)
BL_PWR: C15.1 C16.1 C20.1 C21.1 C50.1 C51.1 C52.1 D4.2(CATHODE) J2.38 J2.39 J2.40 J3.1 J3.2 J3.3 J5.38 J5.39 J5.40 J6.38 J6.40 U10.4(VO)
BOARD_1P8V: C9.1 C23.1 C27.1 C30.1 C32.1 C33.1 C46.1 FB1.1 FB4.2 LP1.1 R3.1 R4.1 R51.1 R53.1 R54.2 R55.2 R56.2 R57.2 R58.2 R59.2 R72.1 R73.1 R74.1 R89.2 R102.2 R103.2 U2.5(VCC) U3.5(SENSE) U3.6(VDD) U4.5(VCC) U5.6(VDDOUT#6) U5.7(VDDOUT#7) U6.3(VCCA) U9.1(OUT#1) U9.18(OUT#18) U9.19(OUT#19) U9.20(OUT#20)
BOARD_3P3V: C28.1 C29.1 C42.1 C45.1 FB2.1 FB3.1 LP7.1 R1.1 R60.2 R61.2 R77.1 R78.1 R82.2 R87.1 R101.2 U6.7(VCCB) U8.1(OUT#1) U8.18(OUT#18) U8.19(OUT#19) U8.20(OUT#20) U9.5(IN#5) U9.6(IN#6) U9.7(IN#7) U9.8(IN#8)
BOARD_5V: C34.1 C37.1 C38.1 C39.1 C41.1 J15.3 LP6.1 R79.1 R83.2 U7.2(VOUT) U8.5(IN#5) U8.6(IN#6) U8.7(IN#7) U8.8(IN#8) U8.10(BIAS) U9.10(BIAS)
BOARD_9V: C40.1 FB5.2 FB6.1 J14.2 J15.1 U7.1(VIN) U7.5(ENABLE)
BOARD_RESETN: C10.1 J16.6 R29.2 R51.2 R52.1 R64.2 U1.B1(EN)
BRD_RST_DIP: R56.1 R64.1 SW2.14(B3)
CDC_CLKY2: R68.1
CDC_CLKY3: R69.1
CDC_S0: J7.1 R74.2 U5.2(S0)
CDC_S1_SDA: J8.1 J18.1 R73.2 U5.13(S1_SDA)
CDC_S2_SCL: J11.1 J19.1 R72.2 U5.12(S2_SCL)
CDC_VDD: C31.1 FB4.1 U5.3(VDD)
CDC_XIN: C25.2 R66.1 U5.1(XIN_CLK) Y1.3(XO)
CDC_XOUT: C26.2 R66.2 U5.14(XOUT) Y1.1(XI)
CDC_Y1: R67.2 U5.11(Y1)
CDC_Y2: R68.2 U5.9(Y2)
CDC_Y3: R69.2 U5.8(Y3)
CT: C22.1 U3.4(CT)
DIMMINGCTRL: J16.4 R100.2 U10.11(DCTRL)
DSI_A0N: J4.35 R9.1 U1.J3(DA0N)
DSI_A0P: J4.33 R8.1 U1.H3(DA0P)
DSI_A1N: J4.27 R11.1 U1.J4(DA1N)
DSI_A1P: J4.25 R10.1 U1.H4(DA1P)
DSI_A2N: J4.11 R13.1 U1.J6(DA2N)
DSI_A2P: J4.9 R12.1 U1.H6(DA2P)
DSI_A3N: J4.3 R15.1 U1.J7(DA3N)
DSI_A3P: J4.1 R14.1 U1.H7(DA3P)
DSI_ACLKN: J4.19 R7.1 U1.J5(DACN)
DSI_ACLKP: J4.17 R6.1 U1.H5(DACP)
DSI_B0N: J4.36 U1.C1(DB0N)
DSI_B0P: J4.34 U1.C2(DB0P)
DSI_B1N: J4.28 U1.D1(DB1N)
DSI_B1P: J4.26 U1.D2(DB1P)
DSI_B2N: J4.12 U1.F1(DB2N)
DSI_B2P: J4.10 U1.F2(DB2P)
DSI_B3N: J4.4 U1.G1(DB3N)
DSI_B3P: J4.2 U1.G2(DB3P)
DSI_BCLKN: J4.20 U1.E1(DBCN)
DSI_BCLKP: J4.18 U1.E2(DBCP)
EN1P8: C47.1 R87.2 U9.11(EN)
EN3P3: C43.1 R79.2 U8.11(EN)
EXT_BKLT_9V: C49.1 FB6.2 Q1.4(SOURCE) R91.2 R92.2 TP4.1(TP)
EXT_REFCLK: J17.1 R105.1
FB_1PT8V: R89.1 R90.2 U9.16(FB)
FB_3PT3V: R82.1 R84.2 U8.16(FB)
FLATA_20455_CLKN: J2.17 R23.2
FLATA_20455_CLKP: J2.18 R24.2
FLATA_20455_YN0: J2.8 R17.2
FLATA_20455_YN1: J2.11 R19.2
FLATA_20455_YN2: J2.14 R21.2
FLATA_20455_YN3: J2.20 R26.2
FLATA_20455_YP0: J2.9 R18.2
FLATA_20455_YP1: J2.12 R20.2
FLATA_20455_YP2: J2.15 R22.2
FLATA_20455_YP3: J2.21 R25.2
FLATB_20455_CLKN: J5.17 R45.2
FLATB_20455_CLKP: J5.18 R46.2
FLATB_20455_YN0: J5.8 R42.2
FLATB_20455_YN1: J5.11 R40.2
FLATB_20455_YN2: J5.14 R44.2
FLATB_20455_YN3: J5.20 R47.2
FLATB_20455_YP0: J5.9 R39.2
FLATB_20455_YP1: J5.12 R41.2
FLATB_20455_YP2: J5.15 R43.2
FLATB_20455_YP3: J5.21 R48.2
FLATCHA_CLKN: J6.13 R23.1 U1.F9(A_CLKN)
FLATCHA_CLKP: J6.15 R24.1 U1.F8(A_CLKP)
FLATCHA_Y0N: J6.1 R17.1 U1.C9(A_Y0N)
FLATCHA_Y0P: J6.3 R18.1 U1.C8(A_Y0P)
FLATCHA_Y1N: J6.5 R19.1 U1.D9(A_Y1N)
FLATCHA_Y1P: J6.7 R20.1 U1.D8(A_Y1P)
FLATCHA_Y2N: J6.9 R21.1 U1.E9(A_Y2N)
FLATCHA_Y2P: J6.11 R22.1 U1.E8(A_Y2P)
FLATCHA_Y3N: J6.17 R26.1 U1.G9(A_Y3N)
FLATCHA_Y3P: J6.19 R25.1 U1.G8(A_Y3P)
FLATCHB_CLKN: J6.14 R45.1 U1.A6(B_CLKN)
FLATCHB_CLKP: J6.16 R46.1 U1.B6(B_CLKP)
FLATCHB_Y0N: J6.2 R42.1 U1.A3(B_Y0N)
FLATCHB_Y0P: J6.4 R39.1 U1.B3(B_Y0P)
FLATCHB_Y1N: J6.6 R40.1 U1.A4(B_Y1N)
FLATCHB_Y1P: J6.8 R41.1 U1.B4(B_Y1P)
FLATCHB_Y2N: J6.10 R44.1 U1.A5(B_Y2N)
FLATCHB_Y2P: J6.12 R43.1 U1.B5(B_Y2P)
FLATCHB_Y3N: J6.18 R47.1 U1.A7(B_Y3N)
FLATCHB_Y3P: J6.20 R48.1 U1.B7(B_Y3P)
FX_CLKN: J1.13(P13) R7.2
FX_CLKP: J1.11(P11) R6.2
FX_N0: J1.19(P19) R9.2
FX_N1: J1.25(P25) R11.2
FX_N2: J1.31(P31) R13.2
FX_N3: J1.37(P37) R15.2
FX_P0: J1.17(P17) R8.2
FX_P1: J1.23(P23) R10.2
FX_P2: J1.29(P29) R12.2
FX_P3: J1.35(P35) R14.2
GP_DIP: J16.5 R54.1 R63.1 R100.1 SW2.16(B1)
GPIO: J1.34(P34) XC7.1
I2C_3V3EN: R55.1 SW2.15(B2) U6.6(OE)
I2C_SCL: J1.18(P18) J4.40 J19.2 R3.2 R76.1 U1.H1(SCL)
I2C_SCL_3P3V: J10.1 R77.2 U6.1(B2)
I2C_SDA: J1.20(P20) J4.39 J18.2 R4.2 R75.1 U1.J1(SDA)
I2C_SDA_3P3V: J10.3(2) R78.2 U6.8(B1)
IFB1: J2.31 J3.11 J6.29 R99.1
IFB2: J2.32 J3.10 J6.31 R98.1
IFB3: J2.33 J3.9 J6.33 R97.1
IFB4: J3.8 J5.31 J6.35 R96.1
IFB5: J3.7 J5.32 J6.37 R95.1
IFB6: J3.6 J5.33 J6.39 R94.1
IRQ: R16.2 R70.2 TP1.1(TP) U1.J9(IRQ) U2.2(A)
IRQ_LED: D1.1(A) R2.1
IRQ_OUT: R1.2 R2.2 U2.4(Y)
J6_3P3V: J6.28 R106.2 R107.2 XC12.1
J6_26: J6.26 R107.1
LED9V: D3.1(A) R81.1
LED_BKLT_EN: J16.3 R63.2 U10.15(EN)
LED_EN: J6.32 J16.8 R27.2 R28.2 R49.2 R50.2 R61.1 SW2.9(B8)
LVDS_REFCLK: C55.1 R67.1 R104.1
PANEL_3P3V: C12.1 C13.1 C14.1 C17.1 C18.1 C19.1 FB2.2 FB3.2 J2.2 J2.3 J5.2 J5.3 R106.1
PG: R80.1 R88.1 R103.1 U4.1(A)
PG1P8: R88.2 U9.9(PG)
PG3P3: R80.2 U8.9(PG)
PWM1: J1.10(P10) XC5.1
PWR_IN: C35.1 C36.1 FB5.1 J15.2 R81.2 SW6.2
PWRIN_SW: D2.1(C) SW6.1
Q1_PIN2: D5.3(CATHODE) L1.2 Q1.2(NC) Q1.3(DRAIN)
REFCLK: R5.1 R104.2 R105.2 U1.H2(REFCLK)
RESET#: R52.2 U3.1(RESET#)
S_PWMIN: J2.35 J5.35 J6.30 J16.9 R27.1 R49.1 R60.1 SW2.10(B7)
SS1P8: C48.1 U9.15(SS)
SS3P3: C44.1 U8.15(SS)
TE: J1.38(P38) XC8.1
TEST1: R62.2 U1.H8(TEST1)
TEST1_DIP: R57.1 R62.1 SW2.13(B4)
TEST2: R65.2 U1.B2(TEST2)
TEST2_DIP: R58.1 R65.1 SW2.12(B5)
TIMER_PWM: J1.30(P30) XC6.1
VCORE_1P1_OUT: C11.1 LP3.1 U1.J8(VCORE)
N15262521: J1.24(P24) R16.1
N16337340: U3.3(MR#) U4.4(Y)
N16337368: C24.1 R53.2 SW1.3(B_) SW1.4(B) U4.2(B)
N16343227: J2.36 R28.1
N16438569: J14.1 R86.1
N16449790: J5.36 R50.1
N16485912: D6.1(A) R101.1
N16486116: D7.1(A) R102.1
N16547062: J6.27 XC11.2
N16547066: J6.25 XC9.2
N16553551: J4.38 R70.1
N16621879: J16.1 XC15.1
N16621883: J16.2 XC14.1
N16649721: J4.37 R29.1
N152624671: J1.1(P1) XC1.2
N152624910: J1.2(P2) XC4.1
N152625630: J1.4(P4) XC3.1
N152625791: J1.3(P3) XC2.2

Pads without a net: D5 2; J1 5 6 7 8 14 16 26 28 36; J2 1 4 5 6 7 23 24 26 27 29 30 34 37; J3 4 5; J5 1 4 5 6 7 23 24 26 27 29 30 34 37; J10 4 5 6 7 8 9; NOREF 1; NOREF#5 1; NOREF#7 1; NOREF#9 1; NOREF#11 1; NOREF#12 1; NOREF#18 1; NOREF#19 1; NOREF#20 1; SW6 3; U2 1; U5 4; XC1 1; XC2 1; XC3 2; XC4 2; XC5 2; XC6 2; XC7 2; XC8 2; XC9 1; XC11 1; XC12 2; XC14 2; XC15 2

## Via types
v1: diameter 0.406, hole 0.203, TOP to BOTTOM, 501 vias
v2: diameter 0.254, hole 0.127, TOP to BOTTOM, 55 vias
v3: diameter 0.33, hole 0.152, TOP to BOTTOM, 60 vias

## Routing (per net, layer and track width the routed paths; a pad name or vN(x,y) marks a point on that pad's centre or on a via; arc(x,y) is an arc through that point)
5V_AJD: length 5.4
  TOP w0.508: R85.2 C41.2 42.79,94.3 R83.1 41.85,95.94 41.85,95.95 U7.4
9V_DIODE: length 8.3
  TOP w1.016: J13.1 22.99,106.9 D2.2
GND: length 459.6
  TOP w0.076: v2(39.22,49.31) 38.81,48.9 U1.A8 ; U1.B9 39.3,48.45 39.76,48.91 v2(39.87,48.91) ; U1.A2 35.8,49.16 v2(35.59,49.38)
  TOP w0.254: v1(3.71,44.36) 4.35,44.36 v3(4.36,44.37) ; U1.F4 36.58,46.4 v2(36.5,46.48) ; v1(9.67,41.36) 11.13,41.36 J4.7 ; v1(13.95,14.73) 14.2,14.73 14.83,14.1 J1.40 ; v2(37.03,47.59) 37.23,47.4 U1.D5 ; v1(18.93,10.21) 19.22,10.21 19.63,9.81 J1.27 ; J4.31 11.13,50.36 v1(9.72,50.36) ; J4.13 11.13,43.86 v1(9.78,43.86) ; v1(9.77,46.86) 11.13,46.86 J4.21 ; v1(9.72,44.36) 11.13,44.36 J4.15 ; J6.24 67.79,44.22 67.8,44.22 v1(69.22,44.22) ; v2(37.04,45.93) 37.3,46.19 U1.F5 ; J6.36 67.79,39.72 v1(66.39,39.72) ; J4.5 11.13,40.86 v1(9.7,40.86) ; v1(15.64,10.23) 15.25,10.23 14.83,9.81 J1.39 ; v1(3.71,46.86) 4.35,46.86 v3(4.36,46.87) ; v2(36.5,46.87) 36.53,46.9 U1.E4 ; v1(3.71,47.36) 5.39,47.36 J4.24 ; v3(4.36,49.86) 4.36,49.86 v1(3.71,49.86) ; v2(39.63,45.38) 39.61,45.4 U1.H9 ; v1(3.71,41.36) 5.39,41.36 J4.8 ; v1(22.74,10.42) 22.4,10.42 22.03,10.8 J1.22 ; v1(17.94,10.28) 17.7,10.28 17.23,9.81 J1.33 ; J4.6 5.39,40.86 v1(3.71,40.86) ; J4.23 11.13,47.36 v1(9.71,47.36) ; v1(69.21,44.72) 67.8,44.72 67.79,44.72 J6.22 ; v1(63.41,44.22) 62.06,44.22 62.05,44.22 J6.23 ; J1.21 22.03,9.81 21.6,10.23 v1(21.23,10.23) ; v3(4.35,43.86) 4.35,43.86 v1(3.71,43.86) ; v1(3.71,50.36) v3(4.36,50.36) ; J6.21 62.05,44.72 62.06,44.72 v1(63.38,44.72) ; J1.15 24.43,9.81 24.09,10.14 v1(23.71,10.14) ; U6.2 v1(75.45,94.69) ; v1(66.34,40.22) 67.79,40.22 J6.34 ; J4.29 11.13,49.86 v1(9.76,49.86)
  TOP w0.356: v1(31.78,67.72) 31.78,67.71 U9.2 ; J5.GND3 v1(89.61,29.81) ; J5.GND3 v1(91.08,28.77) ; J5.GND3 v1(92.52,29.81) ; J5.GND3 v1(91.08,30.9) ; J2.22 v1(87.83,74.93) ; SW2.7 v1(25.91,67.15) ; J6.G3 64.94,41.79 v1(65.44,42.3) ; J6.G3 J6.G2 64.92,49.27 ; J6.G3 J6.G4 64.92,36.9 64.93,36.9 v1(64.93,35.34) ; C47.2 v1(40.79,63.93) ; v1(38.25,67.72) 38.25,67.71 U9.14 ; U8.12 43.71,77.93 v1(43.71,77.93) ; SW2.3 v1(20.83,67.26) ; C24.2 v1(4.55,89.55) ; v1(35.66,70.29) 35.65,70.28 U9.17 ; v1(38.25,67.06) 38.25,67.06 U9.13 ; J5.22 v1(87.52,41.91) ; U7.6 v1(42.84,103.37) ; U7.6 v1(40.58,101.75) ; U7.6 v1(38.35,103.37) ; SW2.4 v1(22.1,67.32) ; J2.GND2 v1(88.46,64.57) ; U8.2 v1(37.26,79.23) ; U9.3 31.75,67.06 v1(31.75,67.06) ; C50.2 v1(70.87,80.08) ; C50.2 v1(69.66,80.92) ; C50.2 v1(71.91,80.92) ; C9.2 v1(54.57,35.23) ; U9.4 31.76,66.41 v1(31.75,66.4) ; C45.2 v1(34.96,60.22) ; C45.2 v1(33.73,59.6) ; C45.2 v1(32.42,60.22) ; C23.2 v1(7.83,91.24) ; J2.GND4 v1(91.08,89.56) ; J2.GND4 v1(92.46,88.53) ; J2.GND4 v1(91.08,87.51) ; J2.GND4 v1(89.74,88.53) ; R90.1 v1(37.29,73.65) ; D3.2 v1(25.98,94.33) ; v1(41.1,81.74) 41.09,81.73 U8.17 ; J5.28 v1(87.43,38.91) ; J2.16 v1(87.63,77.93) ; 64.92,53.03 v1(64.92,51.59) 64.92,49.27 ; J5.GND4 v1(92.44,55.51) ; R93.1 v1(74.14,80.08) ; SW2.8 v1(27.18,67.15) ; C54.2 v1(75.39,79.77) ; J2.28 v1(87.72,71.93) ; J5.10 v1(87.56,47.91) ; U3.2 v1(8.17,100.81) ; v1(43.66,79.23) 43.66,79.23 U8.14 ; 64.92,49.27 v1(65.44,49.79) ; SW2.6 v1(24.64,67.28) ; R86.2 v1(44.19,98.74) ; C39.2 v1(44.19,72.1) ; C39.2 v1(42.84,71.21) ; C39.2 v1(41.58,72.1) ; C22.2 v1(2.39,100.7) ; C46.2 v1(32.93,73.79) ; C46.2 v1(30.45,73.79) ; C46.2 v1(31.79,74.75) ; v1(36.26,85.24) C42.2 v1(37.47,86.2) ; v1(38.25,66.4) 38.24,66.41 U9.12 ; J5.16 v1(87.51,44.91) ; U2.3 v1(51.34,32.51) ; SW2.2 v1(19.56,67.32) ; C43.2 v1(46.07,75.66) ; U7.3 v1(40.58,96.15) ; C15.2 v1(79.87,63.72) ; C37.2 v1(37.98,91.06) ; v1(43.69,78.57) 43.68,78.58 U8.13 ; D6.2 v1(40.13,88.92) ; U8.3 37.27,78.58 v1(37.26,78.57) ; v1(3.89,74.96) SW1.1 v1(3.89,70.95) ; J1.12 v1(26.03,14.95) ; C49.2 v1(61.83,89.33) ; v1(37.26,77.93) 37.27,77.93 U8.4 ; v1(3.89,77.57) SW1.2 3.96,79.58 v1(3.96,81.58) ; SW2.5 v1(23.37,67.26) ; C40.2 v1(44.77,95.72) ; D7.2 v1(33.34,76.58) ; D7.2 v1(35.81,76.58) ; D7.2 v1(34.57,77.67) ; R85.1 v1(43.84,91.94) ; C36.2 v1(23.87,97.07) ; J5.13 v1(87.6,46.41) ; J1.32 v1(18.03,14.87) ; C38.2 v1(32.77,93.81) ; C38.2 v1(34.64,92.65) ; C38.2 v1(34.57,94.83) ; J1.9 v1(26.83,9.99) ; J5.25 v1(87.41,40.41) ; D5.1 v1(63.45,96.37) ; SW2.1 v1(18.29,67.42) ; C48.2 v1(39.72,70.26) ; D1.2 v1(53.59,28.14) ; J5.19 v1(87.45,43.41) ; U4.3 v1(7.42,95.42) ; v1(21.59,97.18) C35.2 v1(20.49,97.96) ; U10.10 v1(77.56,84.51) ; C16.2 v1(81.37,63.75) ; J2.19 v1(87.76,76.43) ; J2.10 v1(87.63,80.93) ; J2.GND1 v1(88.46,86.94) ; C53.2 v1(70.04,85.52) ; C21.2 v1(80.43,30.85) ; C20.2 v1(81.9,30.82) ; J5.GND1 v1(88.46,54.12) ; J2.GND3 v1(92.36,62.83) ; v1(68.88,80.61) C51.2 v1(68.1,81.42) ; R84.1 v1(42.81,84.96) ; J2.13 v1(87.65,79.43) ; C44.2 v1(44.99,81.64) ; J2.25 v1(87.83,73.43) ; C34.2 v1(40.07,91.92) ; J5.GND2 v1(87.42,32.01) ; U10.1 v1(72.95,85.51)
  TOP w0.508: v1(8.28,36.47) 8.28,38.54 J4.G1 8.28,38.57 v1(8.28,40.31) 8.28,43.43 J4.G2 8.26,46.66 v1(8.28,46.68) 8.28,49.78 J4.G3 J4.G4 8.27,54.69 v1(8.27,56.28)
  L2_GND w0.584: TP6.1 89.24,112.61 ; TP6.1 90.12,111.74 ; TP6.1 88.37,111.74 ; TP6.1 89.24,110.86 ; 81.71,112.03 J3.14 ; J3.14 80.83,112.91 ; J3.14 81.71,113.79 ; J3.14 82.59,112.91 ; 32.15,88.42 J16.10 ; J16.10 33.9,88.42 ; J16.10 33.03,87.54 ; J16.10 33.03,89.29 ; J13.2 14.28,108.07 ; J13.2 14.28,103.9 ; J13.2 16.37,105.99 ; J13.2 12.2,105.99 ; 48.36,80.79 J7.2 ; J7.2 48.36,82.93 ; J7.2 47.29,81.86 ; J7.2 49.43,81.86 ; 39.28,31.53 J17.2 ; J17.2 40.16,32.41 ; J17.2 40.16,30.66 ; J17.2 41.04,31.53 ; J3.12 79.17,113.79 ; J3.12 80.05,112.91 ; J3.12 78.29,112.91 ; J3.12 79.17,112.03 ; 49.07,112.1 J10.2 ; J10.2 49.95,112.97 ; J10.2 48.19,112.97 ; J10.2 49.07,113.85 ; 57.59,80.73 J11.2 ; J11.2 58.66,81.8 ; J11.2 57.59,82.86 ; J11.2 56.52,81.8 ; 12.71,68.3 LP4.1 ; LP4.1 12.71,70.73 ; LP4.1 13.93,69.51 ; LP4.1 11.49,69.51 ; LP5.1 40.27,109.77 ; LP5.1 41.48,108.55 ; LP5.1 40.27,107.33 ; LP5.1 39.05,108.55 ; 51.45,80.8 J8.2 ; J8.2 52.52,81.87 ; J8.2 51.45,82.93 ; J8.2 50.38,81.87 ; 80.83,110.37 J3.13 ; J3.13 82.59,110.37 ; J3.13 81.71,111.25 ; J3.13 81.71,109.49 ; J10.10 60.11,112.97 ; J10.10 59.23,113.85 ; J10.10 59.23,112.1 ; J10.10 58.35,112.97 ; J19.3 60.91,85.41 ; J19.3 60.04,84.53 ; J19.3 61.79,84.53 ; J19.3 60.91,83.66 ; 49.33,89.91 TP5.1 ; TP5.1 48.45,90.79 ; TP5.1 50.2,90.79 ; TP5.1 49.33,91.66 ; 17,109.24 J13.3 ; J13.3 19.08,111.32 ; J13.3 21.17,109.24 ; J13.3 19.08,107.16 ; 53.66,84.53 J18.3 ; J18.3 54.53,85.41 ; J18.3 55.41,84.53 ; J18.3 54.53,83.65
  L3_SIG w0.076: 69.63,39.52 v1(69.58,39.52)
  L3_SIG w0.584: J17.2 41.04,31.53 ; J17.2 39.28,31.53 ; J17.2 40.16,32.41 ; J17.2 40.16,30.66 ; 48.36,80.79 J7.2 ; J7.2 48.36,82.93 ; J7.2 47.29,81.86 ; J7.2 49.43,81.86 ; 54.53,83.65 J18.3 ; J18.3 53.66,84.53 ; J18.3 54.53,85.41 ; J18.3 55.41,84.53 ; 33.03,87.54 J16.10 ; J16.10 33.9,88.42 ; J16.10 33.03,89.29 ; J16.10 32.15,88.42 ; LP5.1 40.27,109.77 ; LP5.1 39.05,108.55 ; LP5.1 41.48,108.55 ; LP5.1 40.27,107.33 ; J19.3 60.91,85.41 ; J19.3 60.91,83.66 ; J19.3 61.79,84.53 ; J19.3 60.04,84.53 ; TP5.1 50.2,90.79 ; TP5.1 48.45,90.79 ; TP5.1 49.33,91.66 ; TP5.1 49.33,89.91 ; 17,109.24 J13.3 ; J13.3 19.08,111.32 ; J13.3 21.17,109.24 ; J13.3 19.08,107.16 ; LP4.1 12.71,70.73 ; LP4.1 12.71,68.3 ; LP4.1 11.49,69.51 ; LP4.1 13.93,69.51 ; J10.10 60.11,112.97 ; J10.10 58.35,112.97 ; J10.10 59.23,113.85 ; J10.10 59.23,112.1 ; J10.2 49.95,112.97 ; J10.2 49.07,112.1 ; J10.2 48.19,112.97 ; J10.2 49.07,113.85 ; J11.2 57.59,82.86 ; J11.2 57.59,80.73 ; J11.2 58.66,81.8 ; J11.2 56.52,81.8 ; J8.2 52.52,81.87 ; J8.2 51.45,82.93 ; J8.2 50.38,81.87 ; J8.2 51.45,80.8 ; J13.2 16.37,105.99 ; J13.2 14.28,103.9 ; J13.2 12.2,105.99 ; J13.2 14.28,108.07
  L5_GND w0.584: TP5.1 49.33,91.66 ; TP5.1 48.45,90.79 ; TP5.1 49.33,89.91 ; TP5.1 50.2,90.79 ; 39.05,108.55 LP5.1 ; LP5.1 41.48,108.55 ; LP5.1 40.27,109.77 ; LP5.1 40.27,107.33 ; J18.3 55.41,84.53 ; J18.3 54.53,83.65 ; J18.3 53.66,84.53 ; J18.3 54.53,85.41 ; J16.10 33.03,89.29 ; J16.10 32.15,88.42 ; J16.10 33.9,88.42 ; J16.10 33.03,87.54 ; 78.29,112.91 J3.12 ; J3.12 79.17,113.79 ; J3.12 80.05,112.91 ; J3.12 79.17,112.03 ; 51.45,80.8 J8.2 ; J8.2 52.52,81.87 ; J8.2 51.45,82.93 ; J8.2 50.38,81.87 ; J19.3 60.91,85.41 ; J19.3 61.79,84.53 ; J19.3 60.91,83.66 ; J19.3 60.04,84.53 ; J13.2 14.28,108.07 ; J13.2 16.37,105.99 ; J13.2 12.2,105.99 ; J13.2 14.28,103.9 ; 58.35,112.97 J10.10 ; J10.10 60.11,112.97 ; J10.10 59.23,112.1 ; J10.10 59.23,113.85 ; 40.16,30.66 J17.2 ; J17.2 41.04,31.53 ; J17.2 39.28,31.53 ; J17.2 40.16,32.41 ; J3.14 81.71,113.79 ; J3.14 82.59,112.91 ; J3.14 80.83,112.91 ; J3.14 81.71,112.03 ; 11.49,69.51 LP4.1 ; LP4.1 13.93,69.51 ; LP4.1 12.71,68.3 ; LP4.1 12.71,70.73 ; 81.71,109.49 J3.13 ; J3.13 82.59,110.37 ; J3.13 80.83,110.37 ; J3.13 81.71,111.25 ; TP6.1 90.12,111.74 ; TP6.1 89.24,112.61 ; TP6.1 88.37,111.74 ; TP6.1 89.24,110.86 ; J10.2 49.95,112.97 ; J10.2 49.07,113.85 ; J10.2 48.19,112.97 ; J10.2 49.07,112.1 ; 57.59,80.73 J11.2 ; J11.2 58.66,81.8 ; J11.2 57.59,82.86 ; J11.2 56.52,81.8 ; 47.29,81.86 J7.2 ; J7.2 49.43,81.86 ; J7.2 48.36,80.79 ; J7.2 48.36,82.93 ; J13.3 19.08,111.32 ; J13.3 17,109.24 ; J13.3 21.17,109.24 ; J13.3 19.08,107.16
  BOTTOM w0.076: C8.2 38.96,49.04 v2(39.22,49.31)
  BOTTOM w0.254: C3.2 37.23,47.4 v2(37.03,47.59) ; C12.2 v1(87.5,90.66) ; C12.2 v1(84.58,90.66) ; C12.2 v1(86.02,91.65) ; C19.2 v1(82.61,52.92) ; C14.2 v1(82.49,85.7) ; v2(36.5,46.87) 36.54,46.92 C5.2 ; v2(36.5,46.48) 36.56,46.42 C7.2 ; C2.2 v1(42.58,46.02) ; C10.2 v2(34.35,49.39) ; C18.2 v1(84.11,53.56) ; C13.2 v1(84.81,85.73) ; v1(84.7,57.84) C17.2 87.7,57.84
  BOTTOM w0.356: C25.1 v1(48.81,27.93) ; v1(38.08,42.56) 38.08,43.18 37.95,43.31 R5.2 ; Y1.2 v1(46.73,31.6) ; U5.10 v1(41.32,24.03) ; C11.2 39.33,38.05 v1(40.06,37.31) ; v1(46.32,29.95) 45.5,29.95 Y1.4 ; C26.1 v1(42.7,29.69) ; v1(42.89,49.49) 42.84,49.43 C1.2 ; C33.2 v1(48.26,19.55) ; C31.2 v1(51.6,23.15) ; C32.2 v1(49.37,19.44) ; C55.2 v1(38.13,23.08) ; C27.2 v1(49.96,19.14) ; C29.2 v1(75.62,96.4) ; C30.2 v1(73.6,93.18) ; C28.2 v1(79.37,93.13) ; U5.5 v1(47.1,24.03)
  vias: v1(30.72,32.24) v1(33.53,27.69) v1(33.87,68.17) v1(33.87,67.4) v1(33.87,66.64) v1(33.87,65.88) v1(34.63,68.17) v1(34.63,65.88) v1(35.4,68.17) v1(35.4,65.88) v1(36.16,68.17) v1(36.16,67.4) v1(36.16,66.64) v1(36.16,65.88) v1(37.46,30.59) v1(39.39,79.63) v1(39.39,78.87) v1(39.39,78.1) v1(39.39,77.34) v1(40.15,79.63) v1(40.15,77.34) v1(40.91,79.63) v1(40.91,77.34) v1(41.67,79.63) v1(41.67,78.87) v1(41.67,78.1) v1(41.67,77.34) v1(44.02,34.83) v1(45.33,39.92) v1(52.83,54.19) v1(55.3,54.22) v1(55.75,52.68) v1(56.45,49.89) v1(57.93,48.64) v1(58.73,46.48) v1(60.32,62) v1(60.91,58.36) v1(61.78,56.47) v1(65.76,75.76) v1(65.79,43.5) v1(66.15,44.6) v1(67.06,73.41) v1(67.45,90.64) v1(67.67,65.35) v1(69.24,79.24) v1(69.76,64.17) v1(70.35,61.84) v1(70.39,59.27) v1(70.31,56.59) v1(71.63,39.6) v1(71.71,78.19) v1(74.7,85.32) v1(74.7,84.76) v1(74.7,84.2) v1(75.26,85.32) v1(75.26,84.2) v1(75.82,85.32) v1(75.82,84.76) v1(75.82,84.2) v1(77.3,53.76) v1(77.66,65.16) v1(78.04,67.01) v1(78.25,63.7) v1(79.57,79.47) v1(83.84,60.19) v1(84.24,74.1) v1(85.18,88.94) v1(85.18,88.13) v1(85.17,55.89) v1(85.17,55.08) v1(85.19,30.2) v1(85.19,29.39) v1(85.84,88.53) v1(85.81,62.83) v1(85.83,55.48) v1(85.85,29.79) v1(86.49,88.94) v1(86.46,63.24) v1(86.48,62.4) v1(86.48,55.89) v1(86.49,55.05) v1(86.5,88.1) v1(86.5,30.2) v1(86.52,29.36) v3(4.36,47.37) v3(4.37,41.36) v3(4.37,40.86)
VCC_1P8V: length 13.3
  TOP w0.076: v2(39.72,48.49) 39.72,48.35 39.53,48.17 39.05,48.17 38.82,48.4 U1.B8 ; v2(39.67,49.32) 39.3,48.95 U1.A9 ; U1.E5 37.24,46.9 v2(36.77,47.37)
  TOP w0.254: U1.E6 v2(38.19,46.9) ; U1.J2 v2(35.8,44.62) ; U1.F6 v2(38.17,46.4) ; U1.D6 v2(38.15,47.4)
  BOTTOM w0.076: 38.81,48.36 C8.1
  BOTTOM w0.254: 40.73,46.16 C2.1
  BOTTOM w0.356: LP2.1 48.16,43.81 47.39,44.58 41.82,44.58 40.96,45.44 ; 40.92,48.33 C1.1 40.6,48.41
  vias: v2(37.6,45.93)
A1_SCL: length 1
  TOP w0.356: R76.2 74.56,93.69 U6.4
A1_SDA: length 1
  TOP w0.356: U6.5 77.42,93.63 R75.2
ADDR: length 45.3
  TOP w0.254: U1.A1 34.84,49.36
  TOP w0.356: J16.7 25.34,88.36 v1(25.34,82.72) 24.68,82.72 R71.2 ; v1(28.91,73.59) 28.3,72.98 28.3,65.69 27.74,65.13 27.74,58.9 33.68,52.96 33.68,51.34 34.84,50.18 34.84,49.36
  BOTTOM w0.356: v1(28.91,73.59) 28.91,79.16 v1(25.34,82.72)
ADDR_DIP: length 9.6
  TOP w0.254: v1(24.66,80.8) 24.66,81.53 R71.1 ; SW2.11 v1(24.64,75)
  TOP w0.356: R59.1 SW2.11
  L3_SIG w0.254: v1(24.64,75) 24.64,77.21 24.02,77.82 24.02,80.16 v1(24.66,80.8)
BKLT_CIN: length 1.7
  TOP w0.356: C54.1 75.01,82.08 U10.6
BKLT_FLT: length 32.6
  TOP w0.356: U10.16 74.51,89.73 72.12,92.12 72.12,95.65 69.82,97.95 58.98,97.95 57.35,96.33 57.35,96.12 R91.1 58.07,91.73 58.09,91.75 Q1.1
BKLT_IFB1: length 11.4
  TOP w0.356: C52.2 72.78,79.49 73.3,78.97 76.56,78.97 76.85,79.26 76.85,79.9 76.86,79.91 R99.2 76.86,81.28 76.85,81.29 76.85,82.2 76.55,82.5 75.8,82.5 75.51,82.79 U10.7
BKLT_IFB2: length 3.1
  TOP w0.356: U10.8 77.34,83.29 77.84,82.79 77.84,82.45 77.85,82.44 R98.2
BKLT_IFB3: length 2.1
  TOP w0.356: R97.2 78.28,83.9 78.17,84.01 U10.9
BKLT_IFB4: length 2.1
  TOP w0.356: U10.12 76.74,85.51 78.26,85.51 78.28,85.53 R96.2
BKLT_IFB5: length 4.2
  TOP w0.356: U10.13 77.74,86.24 78.98,87.47 R95.2
BKLT_IFB6: length 3.6
  TOP w0.356: U10.14 75.51,87.12 76.48,88.09 R94.2
BKLT_ISET: length 1.7
  TOP w0.356: U10.5 74.51,83 74.15,82.65 74.15,82.47 74.14,82.46 R93.2
BKLT_SW: length 10.7
  TOP w0.254: 71.93,85.64 72.55,85.01 U10.2
  TOP w1.016: 71.93,85.64 D4.1 70.69,89.7 L1.1
BKLT_VBAT: length 16.3
  TOP w0.254: 70.93,84.53 73.77,84.53 U10.3
  TOP w1.016: 70.93,84.53 C53.1 68.18,84.53 67.73,84.98 63.51,84.98 62.82,85.68 62.82,88.39 63.59,89.16 R92.1
BL_PWR: length 12.4
  TOP w0.356: C52.1 72.78,83.73 73.06,84.01 U10.4
  L3_SIG w0.584: 69.01,109.49 J3.3 ; J3.3 68.13,110.37 ; J3.3 69.01,111.25 ; J3.3 69.89,110.37 ; 66.47,112.03 J3.2 ; J3.2 65.59,112.91 ; J3.2 67.35,112.91 ; J3.2 66.47,113.79 ; J3.1 67.35,110.37 ; J3.1 66.47,111.25 ; J3.1 66.47,109.49 ; J3.1 65.59,110.37
  vias: v1(65.24,89.66) v1(65.24,89.16) v1(65.24,88.65) v1(65.75,89.66) v1(65.75,89.16) v1(65.75,88.65) v1(65.74,83.24) v1(65.74,82.73) v1(66.25,83.24) v1(66.25,82.73) v1(83.41,66.66) v1(83.86,66.66) v1(84.3,66.66) v1(89.65,103.69) v1(89.65,103.18) v1(89.65,102.68) v1(89.65,102.17) v1(89.65,101.66) v1(90.16,103.69) v1(90.16,103.18) v1(90.16,102.68) v1(90.16,102.17) v1(90.16,101.66) v1(90.2,33.76) v1(90.2,33) v1(90.21,66.73) v1(90.21,65.97) v1(90.66,103.69) v1(90.66,103.18) v1(90.66,102.68) v1(90.66,102.17) v1(90.66,101.66) v1(90.97,66.73) v1(90.97,65.97) v1(90.96,33.76) v1(90.96,33) v1(91.17,103.69) v1(91.17,103.18) v1(91.17,102.68) v1(91.17,102.17) v1(91.17,101.66) v1(91.68,103.69) v1(91.68,103.18) v1(91.68,102.68) v1(91.68,102.17) v1(91.68,101.66)
BOARD_1P8V: length 35
  TOP w0.356: R4.1 v1(15.57,56.69) ; U3.5 v1(3.93,100.81) ; v1(34.37,70.29) 34.35,70.27 U9.19 ; v1(31.78,68.36) 31.78,68.36 U9.1 ; U6.3 v1(73.58,94.19) ; R54.2 v1(18.29,79.41) ; U4.5 v1(5.58,98.48) ; R102.2 v1(33.16,71.73) ; C23.1 v1(7.79,93.49) ; v1(35.03,70.29) 35,70.26 U9.18 ; R59.2 v1(24.64,79.38) ; R89.2 v1(35.03,72.34) ; R56.2 v1(20.83,79.38) ; v1(33.71,70.31) 33.7,70.31 U9.20 ; R51.1 v1(9.76,100.53) ; C9.1 v1(53.55,35.68) ; R103.2 v1(2.41,95.41) ; R57.2 v1(22.1,79.45) ; R55.2 v1(19.56,79.38) ; U2.5 v1(54.33,34.26) ; R53.1 v1(4.62,92.26) ; R3.1 v1(14.81,59.55) ; U3.6 v1(3.93,99.86) ; R58.2 v1(23.37,79.44) ; C46.1 v1(30.42,71.76)
  L4_PWR w0.584: LP1.1 68.27,102.2 ; LP1.1 68.27,99.76 ; LP1.1 67.05,100.98 ; LP1.1 69.49,100.98
  BOTTOM w0.356: v1(73.58,94.19) 73.03,94.19 C30.1 ; C32.1 v1(49.37,22.05) ; FB4.2 v1(50.25,22.95) ; R73.1 v1(39.61,26.41) ; v1(49.44,22.72) 49.43,22.73 U5.7 48.29,22.73 48.29,22.04 v1(48.26,22.01) C33.1 ; C27.1 51.17,21.52 v1(50.6,22.09) ; R74.1 v1(51.55,27.08) ; R72.1 v1(37.32,26.79) ; v1(39.15,51.56) 39.15,51.63 39.02,51.76 FB1.1 v1(38.03,52.34) ; U5.6 v1(49.43,23.38)
BOARD_3P3V: length 25.2
  TOP w0.356: R82.2 v1(39.97,83.09) ; U9.7 34.35,63.85 v1(34.37,63.84) ; U8.18 40.44,81.74 v1(40.44,81.74) ; R61.2 v1(27.18,79.32) ; v1(36.27,83.21) C42.1 v1(37.47,82.46) ; v1(33.68,63.84) 33.7,63.86 U9.6 ; R87.1 v1(38.98,64.59) ; R77.1 v1(73.64,96.32) ; v1(39.8,81.74) 39.79,81.72 U8.19 ; R60.2 v1(25.91,79.39) ; U8.20 39.13,81.71 v1(39.14,81.72) ; R78.1 v1(78.76,94.31) ; v1(56.98,31.78) 56.17,31.78 R1.1 ; v1(31.73,65.77) 31.73,65.76 U9.5 ; U9.8 v1(35,63.81) ; C45.1 v1(34.69,62.26) ; C45.1 v1(33.72,62.75) ; C45.1 v1(32.68,62.26) ; v1(37.26,79.89) 37.27,79.88 U8.1 ; U6.7 v1(78.24,94.69) ; R101.2 v1(38.69,83.15)
  L4_PWR w0.584: 31.22,83.14 LP7.1 ; LP7.1 33.66,83.14 ; LP7.1 32.44,81.92 ; LP7.1 32.44,84.36
  BOTTOM w0.076: FB3.1 82.26,54 ; FB3.1 81.7,53.57 ; FB3.1 82.82,53.57
  BOTTOM w0.356: C29.1 v1(76.64,96.46) ; C28.1 v1(78.36,93.06) ; FB2.1 v1(82.1,86.98)
  vias: v1(82.1,89.27) v1(82.1,88.5) v1(82.1,87.74)
BOARD_5V: length 26.6
  TOP w0.356: C39.1 v1(43.79,74.13) ; C39.1 v1(42.84,74.79) ; C39.1 v1(41.87,74.13) ; v1(41.73,75.37) 41.74,75.37 U8.10 ; C38.1 v1(32.74,96.83) ; C38.1 v1(36.22,97.01) ; C38.1 v1(34.67,98.17) ; v1(39.14,75.42) 39.13,75.43 U8.6 ; U9.10 36.3,63.84 v1(36.3,63.84) ; v1(39.07,93.79) C37.1 v1(38,94.51) ; U7.2 v1(39.31,96.17) ; v1(37.24,77.27) 37.24,77.28 U8.5 ; v1(40.46,75.39) 40.44,75.42 U8.8 ; U8.7 39.79,75.43 v1(39.78,75.42) ; R79.1 v1(44.27,76.04) ; C34.1 v1(40.04,94.63) ; R83.2 v1(40.2,95.25) ; v1(41.23,94.33) C41.1 v1(41.29,92.86)
  L3_SIG w0.584: LP6.1 33.62,106.97 ; LP6.1 33.62,104.53 ; LP6.1 32.4,105.75 ; LP6.1 34.84,105.75 ; 29.22,96.55 J15.3 ; J15.3 30.09,97.42 ; J15.3 28.34,97.42 ; J15.3 29.22,98.3
BOARD_9V: length 16.3
  TOP w0.254: FB6.1 58.62,88.95 v1(58.6,88.96)
  TOP w0.508: 59.29,88.91 FB6.1 ; C40.1 v1(44.01,97.48) 43.89,97.61 U7.5 v1(43.12,99.34) ; v1(38.04,99.14) U7.1 v1(37.22,97.61)
  L4_PWR w0.584: 30.09,102.5 J15.1 29.22,103.38 ; 46.25,97.43 J14.2 ; J14.2 48,97.43 ; J14.2 47.13,96.56 ; J14.2 47.13,98.31
  BOTTOM w0.508: FB5.2 v1(30.92,102.79) ; FB5.2 v1(34.27,102.79) ; FB5.2 v1(32.58,103.92)
BOARD_RESETN: length 109.3
  TOP w0.254: U1.B1 v2(34.79,48.85) 34.1,48.85
  TOP w0.356: R52.1 9.76,98.71 R51.2 ; R64.2 20.82,83.83 22.86,85.87 J16.6 22.92,88.47 22.92,91.22 21.07,93.07 18.38,93.07 12.73,98.72 R51.2 ; R51.2 9.76,96.93 9.76,96.93 9.76,91.69 7.9,89.82 7.9,84.24 11.34,80.79 11.34,77.91 15.83,73.43 15.83,68.27 17.99,66.1 24.29,66.1 26.47,63.92 26.47,58.8 v1(26.49,58.78) 29.38,55.89 29.38,51.89 32.42,48.85 34.1,48.85 ; R29.2 v1(15.33,52.86)
  BOTTOM w0.254: v2(34.79,48.85) 34.77,48.83 C10.1
  BOTTOM w0.356: v1(15.33,52.86) 17.03,52.86 22.94,58.78 v1(26.49,58.78)
BRD_RST_DIP: length 9.5
  TOP w0.254: R64.1 20.81,81.56 v1(20.81,80.85)
  TOP w0.356: v1(20.83,75.02) SW2.14 R56.1
  L3_SIG w0.254: v1(20.83,75.02) 20.83,77.64 20.3,78.17 20.3,80.34 v1(20.81,80.85)
CDC_S0: length 60.8
  TOP w0.356: v1(54.04,63.46) 54.04,65.16 48.36,70.84 J7.1
  BOTTOM w0.356: v1(54.04,63.46) 54.1,63.4 54.1,50.92 56.09,48.92 56.09,33.86 50.41,28.17 R74.2 50.06,25.98 U5.2
CDC_S1_SDA: length 70.1
  TOP w0.356: J18.1 54.41,79.33 J8.1 51.45,74.7 51.87,74.28 v1(51.87,69.97)
  BOTTOM w0.356: U5.13 41.62,25.98 40.99,26.61 40.99,27.51 40.33,28.17 R73.2 39.59,28.78 40.36,29.55 41.23,29.55 48.8,37.13 53.56,37.13 55.13,38.7 55.13,48.04 51.89,51.27 51.89,69.95 v1(51.87,69.97)
CDC_S2_SCL: length 81.4
  TOP w0.356: v1(57.64,74.29) 57.64,79.21 J11.1 57.79,79.45 J19.1
  BOTTOM w0.356: U5.12 41.32,25.33 40.93,25.72 38.95,25.72 38.64,26.04 R72.2 38.48,35.53 39.26,36.32 46.08,36.32 48.82,39.05 53.33,39.05 54.14,39.86 54.14,46.89 49.86,51.18 49.86,70.21 51.32,71.67 55.02,71.67 v1(57.64,74.29)
CDC_VDD: length 3.4
  BOTTOM w0.356: C31.1 51.58,25.15 FB4.1 50.07,25.33 48.29,25.33 U5.3
CDC_XIN: length 9
  BOTTOM w0.356: C25.2 48.04,28.89 46.89,28.89 46,28 R66.1 ; C25.2 48.15,28.84 49.16,28.84 49.77,28.24 49.77,27.08 49.32,26.63 48.29,26.63 U5.1 ; C25.2 48.12,29.44 47.6,29.95 Y1.3
CDC_XOUT: length 7.2
  BOTTOM w0.356: Y1.1 44.44,30.53 R66.2 44.38,28.07 C26.2 42.69,28.05 U5.14
CDC_Y1: length 2
  BOTTOM w0.356: R67.2 40.71,24.68 U5.11
CDC_Y2: length 2.4
  BOTTOM w0.356: U5.9 40.61,23.38 R68.2
CDC_Y3: length 2.4
  BOTTOM w0.356: U5.8 41.15,22.73 41.01,22.59 R69.2
CT: length 1.9
  TOP w0.356: U3.4 4.97,101.76 3.79,101.76 3.74,101.72 C22.1
DIMMINGCTRL: length 75.8
  TOP w0.356: U10.11 76.74,85.01 v1(77.78,85.01) ; R100.2 15.86,84.12 17.82,86.09 17.82,88.38 J16.4
  BOTTOM w0.356: v1(77.78,85.01) 76.6,86.18 47.86,86.18 45.8,84.13 35.18,84.13 33.84,85.46 19.12,85.46 17.78,86.8 J16.4
DSI_A0N: length 42.4
  TOP w0.076: 35.66,43.88 36.18,44.39 36.18,44.76 36.3,44.88 U1.J3
  TOP w0.127: J4.35 12.14,51.87 12.26,51.75 15.6,51.75 15.79,51.56 15.89,51.56 15.97,51.63 16.07,51.63 16.15,51.56 16.15,51.45 16.07,51.38 16.07,51.27 16.15,51.2 16.25,51.2 16.33,51.28 16.43,51.28 16.51,51.2 16.51,51.1 16.43,51.02 16.43,50.91 16.5,50.84 16.61,50.84 16.69,50.92 16.79,50.92 16.87,50.84 16.87,50.74 16.79,50.66 16.79,50.56 16.86,50.48 16.97,50.48 17.04,50.56 17.15,50.56 17.22,50.48 17.22,50.38 17.15,50.3 17.15,50.2 17.22,50.12 17.33,50.12 17.4,50.2 17.51,50.2 17.58,50.12 17.58,50.02 17.51,49.94 17.51,49.84 19.19,48.15 19.77,48.15 20.26,48.64 20.41,48.8 21.29,48.8 21.78,48.31 21.78,47.43 21.62,47.28 21.13,46.79 21.13,46.21 21.54,45.8 22.12,45.8 22.77,46.45 23.57,46.45 24.13,45.88 24.13,45.08 23.49,44.44 23.49,43.86 26.77,40.58 27.32,40.58 27.73,40.99 27.73,41.96 28.3,42.53 29.1,42.53 29.66,41.96 29.66,40.99 30.07,40.58 33.69,40.58 34.58,41.47 34.58,42.79 35.66,43.87 35.66,43.88
  vias: v2(12.18,51.87)
